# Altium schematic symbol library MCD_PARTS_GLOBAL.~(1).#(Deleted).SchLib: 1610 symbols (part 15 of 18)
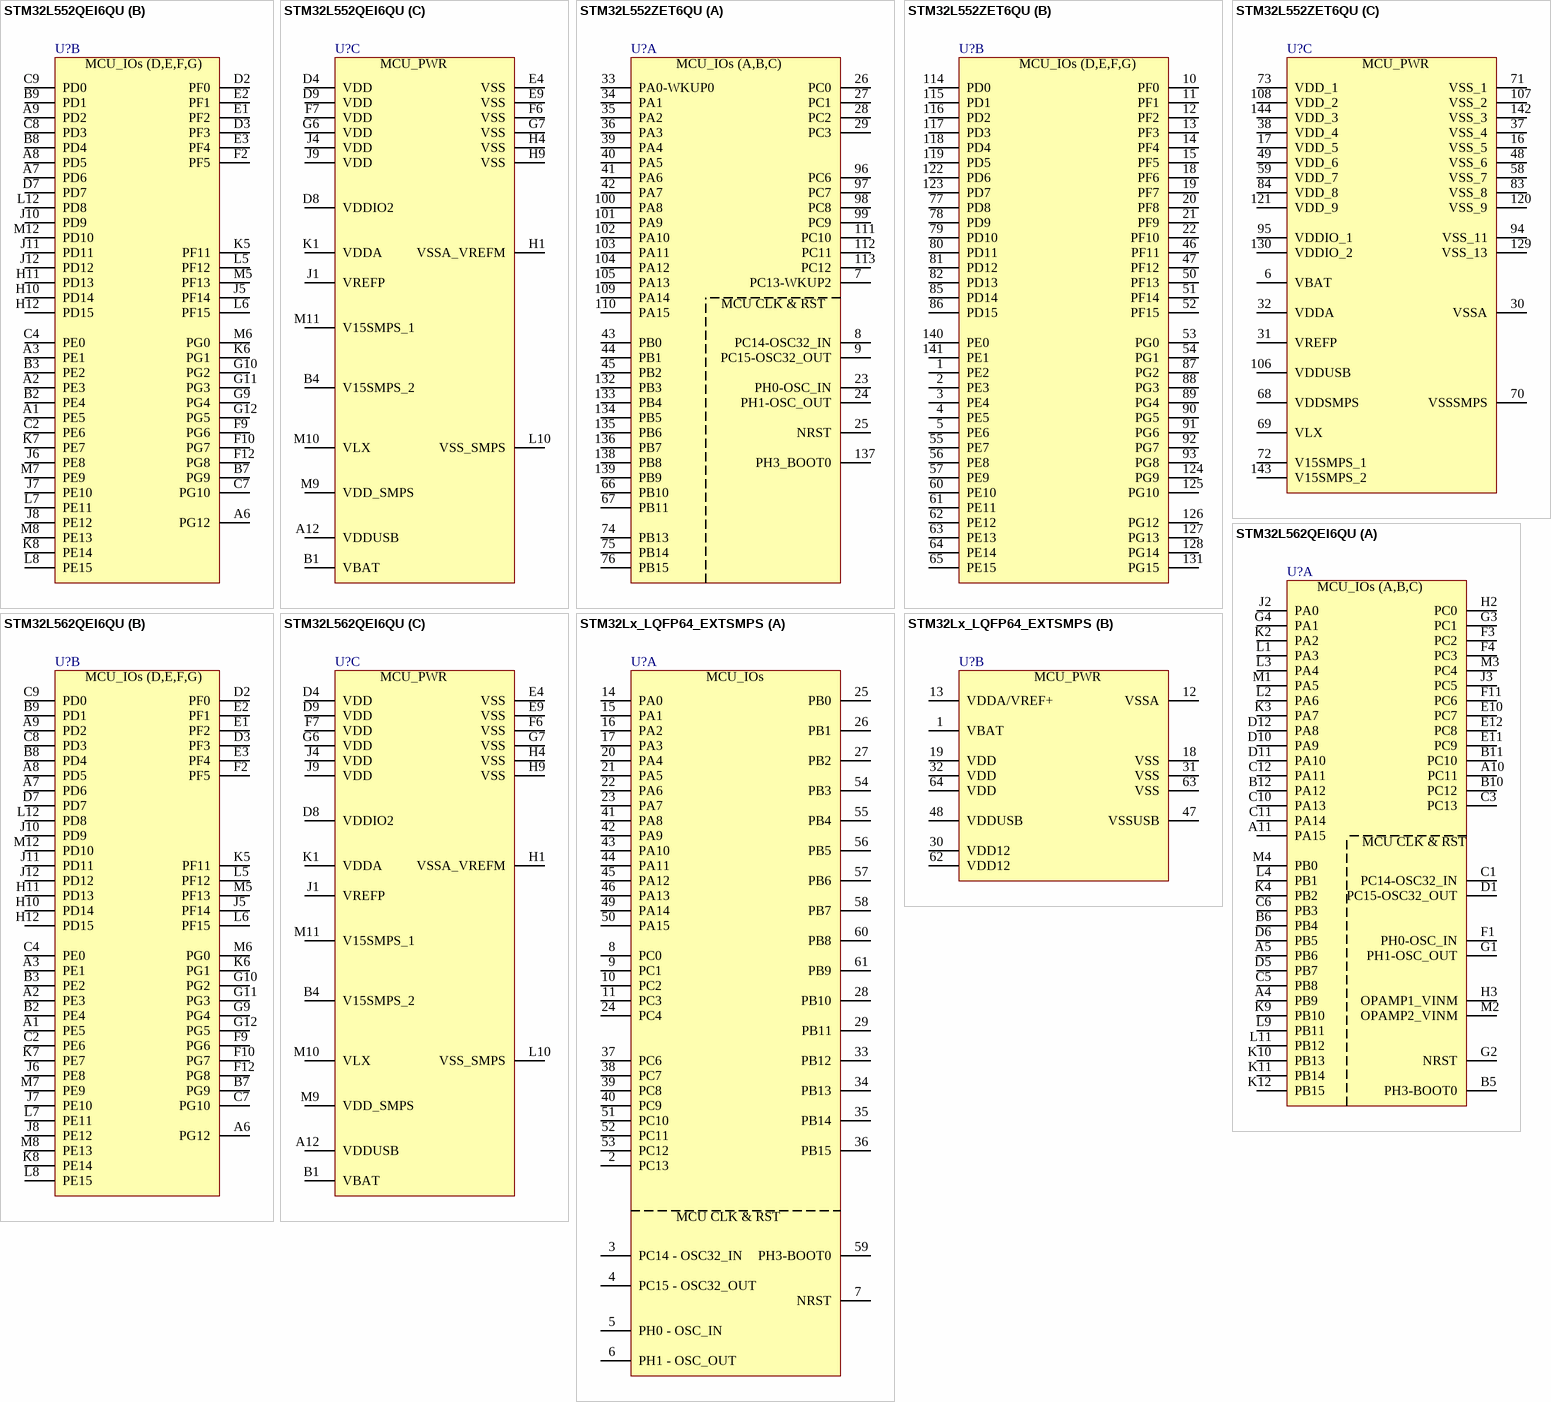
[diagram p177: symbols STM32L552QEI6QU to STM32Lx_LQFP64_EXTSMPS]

## STM32L552ZET6QU
designator U?
part A pins: 7 PC13-WKUP2, 8 PC14-OSC32_IN, 9 PC15-OSC32_OUT, 23 PH0-OSC_IN, 24 PH1-OSC_OUT, 25 NRST, 26 PC0, 27 PC1, 28 PC2, 29 PC3, 33 PA0-WKUP0, 34 PA1, 35 PA2, 36 PA3, 39 PA4, 40 PA5, 41 PA6, 42 PA7, 43 PB0, 44 PB1, 45 PB2, 66 PB10, 67 PB11, 74 PB13, 75 PB14, 76 PB15, 96 PC6, 97 PC7, 98 PC8, 99 PC9, 100 PA8, 101 PA9, 102 PA10, 103 PA11, 104 PA12, 105 PA13, 109 PA14, 110 PA15, 111 PC10, 112 PC11, 113 PC12, 132 PB3, 133 PB4, 134 PB5, 135 PB6, 136 PB7, 137 PH3_BOOT0, 138 PB8, 139 PB9
part B pins: 1 PE2, 2 PE3, 3 PE4, 4 PE5, 5 PE6, 10 PF0, 11 PF1, 12 PF2, 13 PF3, 14 PF4, 15 PF5, 18 PF6, 19 PF7, 20 PF8, 21 PF9, 22 PF10, 46 PF11, 47 PF12, 50 PF13, 51 PF14, 52 PF15, 53 PG0, 54 PG1, 55 PE7, 56 PE8, 57 PE9, 60 PE10, 61 PE11, 62 PE12, 63 PE13, 64 PE14, 65 PE15, 77 PD8, 78 PD9, 79 PD10, 80 PD11, 81 PD12, 82 PD13, 85 PD14, 86 PD15, 87 PG2, 88 PG3, 89 PG4, 90 PG5, 91 PG6, 92 PG7, 93 PG8, 114 PD0, 115 PD1, 116 PD2, 117 PD3, 118 PD4, 119 PD5, 122 PD6, 123 PD7, 124 PG9, 125 PG10, 126 PG12, 127 PG13, 128 PG14, 131 PG15, 140 PE0, 141 PE1
part C pins: 6 VBAT, 16 VSS_5, 17 VDD_5, 30 VSSA, 31 VREFP, 32 VDDA, 37 VSS_4, 38 VDD_4, 48 VSS_6, 49 VDD_6, 58 VSS_7, 59 VDD_7, 68 VDDSMPS, 69 VLX, 70 VSSSMPS, 71 VSS_1, 72 V15SMPS_1, 73 VDD_1, 83 VSS_8, 84 VDD_8, 94 VSS_11, 95 VDDIO_1, 106 VDDUSB, 107 VSS_2, 108 VDD_2, 120 VSS_9, 121 VDD_9, 129 VSS_13, 130 VDDIO_2, 142 VSS_3, 143 V15SMPS_2, 144 VDD_3

## STM32L562QEI6QU
designator U?
part A pins: A4 PB9, A5 PB6, A10 PC11, A11 PA15, B5 PH3-BOOT0, B6 PB4, B10 PC12, B11 PC10, B12 PA12, C1 PC14-OSC32_IN, C3 PC13, C5 PB8, C6 PB3, C10 PA13, C11 PA14, C12 PA11, D1 PC15-OSC32_OUT, D5 PB7, D6 PB5, D10 PA9, D11 PA10, D12 PA8, E10 PC7, E11 PC9, E12 PC8, F1 PH0-OSC_IN, F3 PC2, F4 PC3, F11 PC6, G1 PH1-OSC_OUT, G2 NRST, G3 PC1, G4 PA1, H2 PC0, H3 OPAMP1_VINM, J2 PA0, J3 PC5, K2 PA2, K3 PA7, K4 PB2, K9 PB10, K10 PB13, K11 PB14, K12 PB15, L1 PA3, L2 PA6, L3 PA4, L4 PB1, L9 PB11, L11 PB12, M1 PA5, M2 OPAMP2_VINM, M3 PC4, M4 PB0
part B pins: A1 PE5, A2 PE3, A3 PE1, A6 PG12, A7 PD6, A8 PD5, A9 PD2, B2 PE4, B3 PE2, B7 PG9, B8 PD4, B9 PD1, C2 PE6, C4 PE0, C7 PG10, C8 PD3, C9 PD0, D2 PF0, D3 PF3, D7 PD7, E1 PF2, E2 PF1, E3 PF4, F2 PF5, F9 PG6, F10 PG7, F12 PG8, G9 PG4, G10 PG2, G11 PG3, G12 PG5, H10 PD14, H11 PD13, H12 PD15, J5 PF14, J6 PE8, J7 PE10, J8 PE12, J10 PD9, J11 PD11, J12 PD12, K5 PF11, K6 PG1, K7 PE7, K8 PE14, L5 PF12, L6 PF15, L7 PE11, L8 PE15, L12 PD8, M5 PF13, M6 PG0, M7 PE9, M8 PE13, M12 PD10
part C pins: A12 VDDUSB, B1 VBAT, B4 V15SMPS_2, D4 VDD, D8 VDDIO2, D9 VDD, E4 VSS, E9 VSS, F6 VSS, F7 VDD, G6 VDD, G7 VSS, H1 VSSA_VREFM, H4 VSS, H9 VSS, J1 VREFP, J4 VDD, J9 VDD, K1 VDDA, L10 VSS_SMPS, M9 VDD_SMPS, M10 VLX, M11 V15SMPS_1

## STM32Lx_LQFP64_EXTSMPS
designator U?
part A pins: 2 PC13, 3 PC14 - OSC32_IN, 4 PC15 - OSC32_OUT, 5 PH0 - OSC_IN, 6 PH1 - OSC_OUT, 7 NRST, 8 PC0, 9 PC1, 10 PC2, 11 PC3, 14 PA0, 15 PA1, 16 PA2, 17 PA3, 20 PA4, 21 PA5, 22 PA6, 23 PA7, 24 PC4, 25 PB0, 26 PB1, 27 PB2, 28 PB10, 29 PB11, 33 PB12, 34 PB13, 35 PB14, 36 PB15, 37 PC6, 38 PC7, 39 PC8, 40 PC9, 41 PA8, 42 PA9, 43 PA10, 44 PA11, 45 PA12, 46 PA13, 49 PA14, 50 PA15, 51 PC10, 52 PC11, 53 PC12, 54 PB3, 55 PB4, 56 PB5, 57 PB6, 58 PB7, 59 PH3-BOOT0, 60 PB8, 61 PB9
part B pins: 1 VBAT, 12 VSSA, 13 VDDA/VREF+, 18 VSS, 19 VDD, 30 VDD12, 31 VSS, 32 VDD, 47 VSSUSB, 48 VDDUSB, 62 VDD12, 63 VSS, 64 VDD

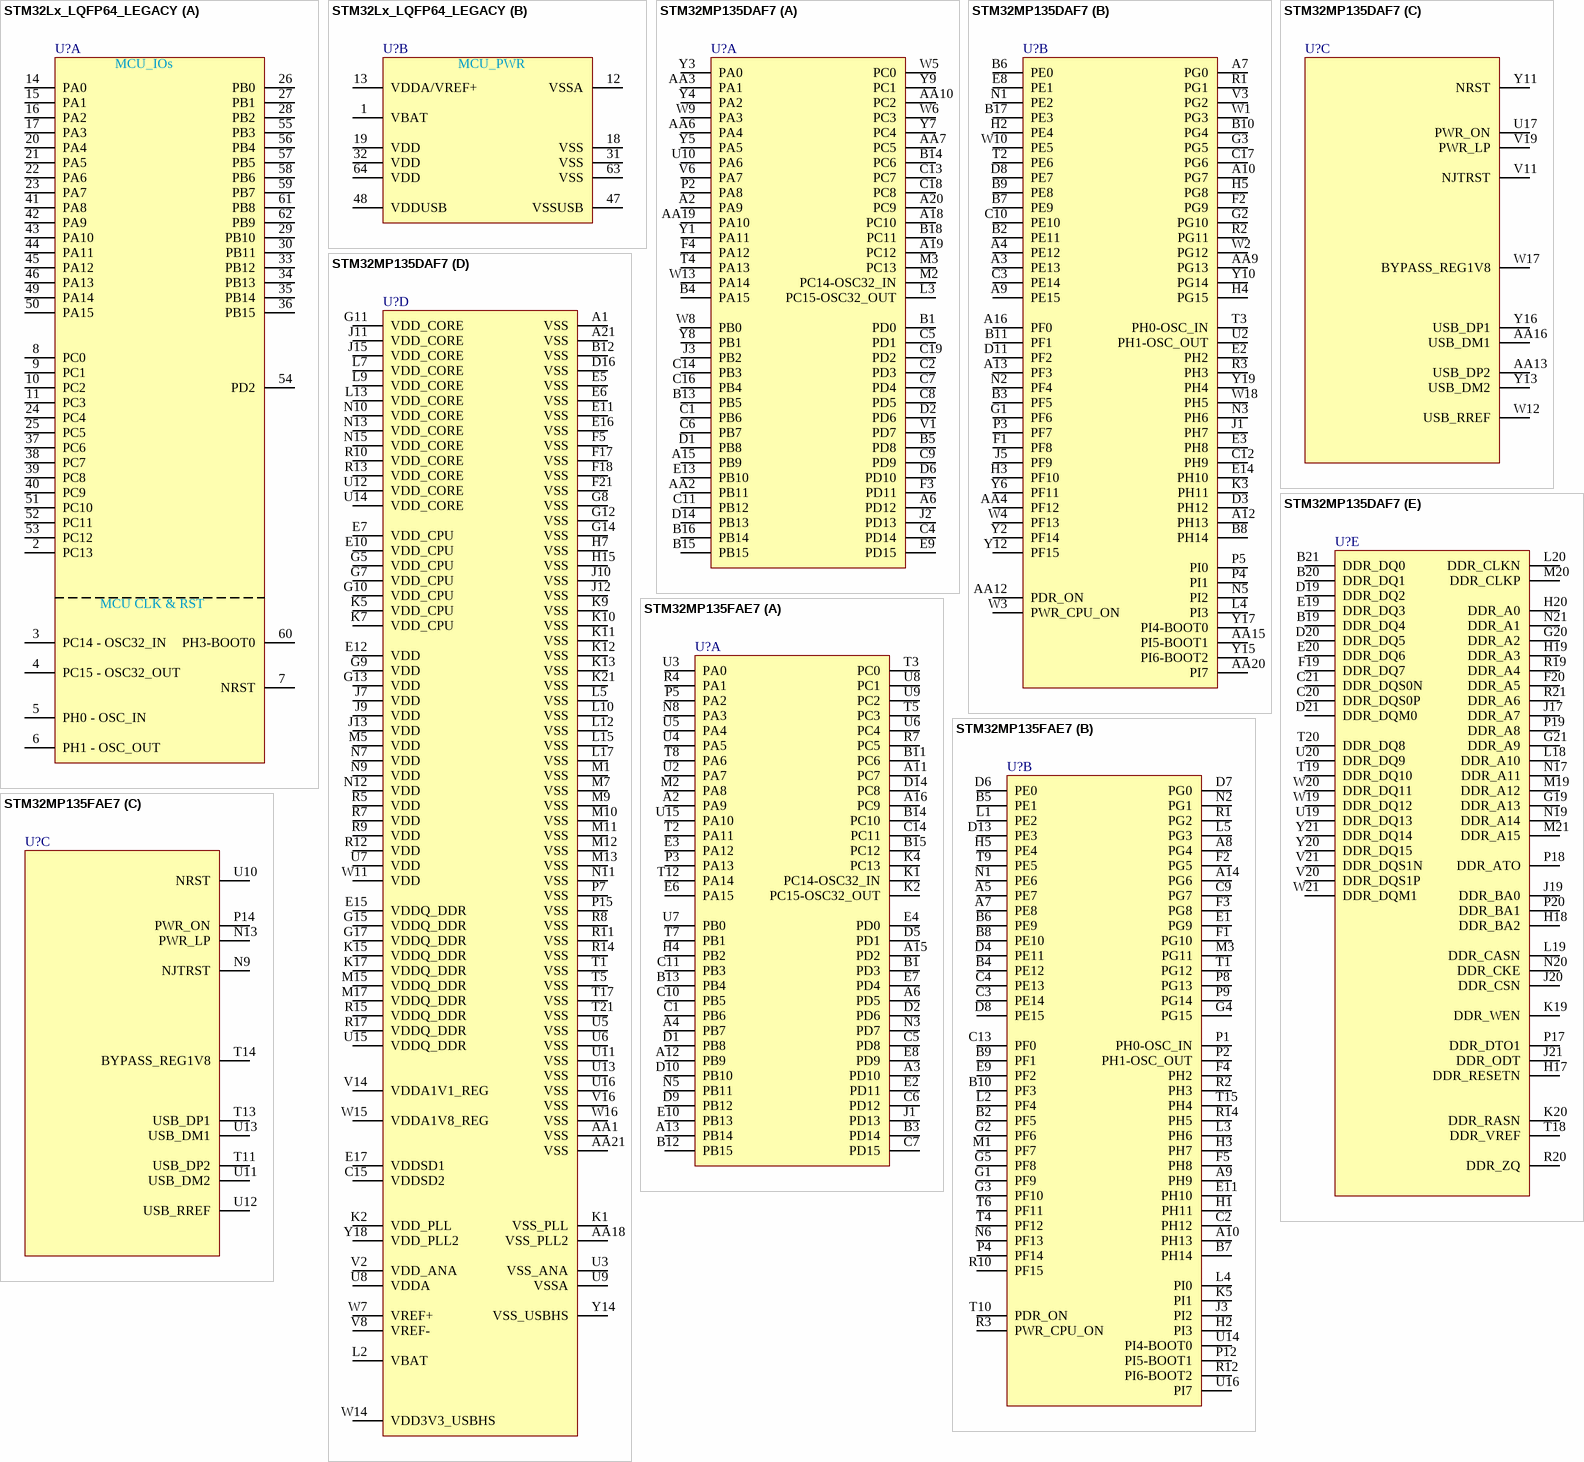
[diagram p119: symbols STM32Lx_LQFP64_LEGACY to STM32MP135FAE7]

## STM32Lx_LQFP64_LEGACY
designator U?
part A pins: 2 PC13, 3 PC14 - OSC32_IN, 4 PC15 - OSC32_OUT, 5 PH0 - OSC_IN, 6 PH1 - OSC_OUT, 7 NRST, 8 PC0, 9 PC1, 10 PC2, 11 PC3, 14 PA0, 15 PA1, 16 PA2, 17 PA3, 20 PA4, 21 PA5, 22 PA6, 23 PA7, 24 PC4, 25 PC5, 26 PB0, 27 PB1, 28 PB2, 29 PB10, 30 PB11, 33 PB12, 34 PB13, 35 PB14, 36 PB15, 37 PC6, 38 PC7, 39 PC8, 40 PC9, 41 PA8, 42 PA9, 43 PA10, 44 PA11, 45 PA12, 46 PA13, 49 PA14, 50 PA15, 51 PC10, 52 PC11, 53 PC12, 54 PD2, 55 PB3, 56 PB4, 57 PB5, 58 PB6, 59 PB7, 60 PH3-BOOT0, 61 PB8, 62 PB9
part B pins: 1 VBAT, 12 VSSA, 13 VDDA/VREF+, 18 VSS, 19 VDD, 31 VSS, 32 VDD, 47 VSSUSB, 48 VDDUSB, 63 VSS, 64 VDD

## STM32MP135DAF7
designator U?
part A pins: A2 PA9, A6 PD12, A15 PB9, A18 PC10, A19 PC12, A20 PC9, AA2 PB11, AA3 PA1, AA6 PA4, AA7 PC5, AA10 PC2, AA19 PA10, B1 PD0, B4 PA15, B5 PD8, B13 PB5, B14 PC6, B15 PB15, B16 PB14, B18 PC11, C1 PB6, C2 PD3, C4 PD14, C5 PD1, C6 PB7, C7 PD4, C8 PD5, C9 PD9, C11 PB12, C13 PC7, C14 PB3, C16 PB4, C18 PC8, C19 PD2, D1 PB8, D2 PD6, D6 PD10, D14 PB13, E9 PD15, E13 PB10, F3 PD11, F4 PA12, J2 PD13, J3 PB2, L3 PC15-OSC32_OUT, M2 PC14-OSC32_IN, M3 PC13, P2 PA8, T4 PA13, U10 PA6, V1 PD7, V6 PA7, W5 PC0, W6 PC3, W8 PB0, W9 PA3, W13 PA14, Y1 PA11, Y3 PA0, Y4 PA2, Y5 PA5, Y7 PC4, Y8 PB1, Y9 PC1
part B pins: A3 PE13, A4 PE12, A7 PG0, A9 PE15, A10 PG7, A12 PH13, A13 PF3, A16 PF0, AA4 PF12, AA9 PG13, AA12 PDR_ON, AA15 PI5-BOOT1, AA20 PI7, B2 PE11, B3 PF5, B6 PE0, B7 PE9, B8 PH14, B9 PE8, B10 PG4, B11 PF1, B17 PE3, C3 PE14, C10 PE10, C12 PH9, C17 PG6, D3 PH12, D8 PE7, D11 PF2, E2 PH2, E3 PH8, E8 PE1, E14 PH10, F1 PF8, F2 PG9, G1 PF6, G2 PG10, G3 PG5, H2 PE4, H3 PF10, H4 PG15, H5 PG8, J1 PH7, J5 PF9, K3 PH11, L4 PI3, N1 PE2, N2 PF4, N3 PH6, N5 PI2, P3 PF7, P4 PI1, P5 PI0, R1 PG1, R2 PG11, R3 PH3, T2 PE6, T3 PH0-OSC_IN, U2 PH1-OSC_OUT, V3 PG2, W1 PG3, W2 PG12, W3 PWR_CPU_ON, W4 PF13, W10 PE5, W18 PH5, Y2 PF14, Y6 PF11, Y10 PG14, Y12 PF15, Y15 PI6-BOOT2, Y17 PI4-BOOT0, Y19 PH4
part C pins: AA13 USB_DP2, AA16 USB_DM1, U17 PWR_ON, V11 NJTRST, V19 PWR_LP, W12 USB_RREF, W17 BYPASS_REG1V8, Y11 NRST, Y13 USB_DM2, Y16 USB_DP1
part D pins: A1 VSS, A21 VSS, AA1 VSS, AA18 VSS_PLL2, AA21 VSS, B12 VSS, C15 VDDSD2, D16 VSS, E5 VSS, E6 VSS, E7 VDD_CPU, E10 VDD_CPU, E11 VSS, E12 VDD, E15 VDDQ_DDR, E16 VSS, E17 VDDSD1, F5 VSS, F17 VSS, F18 VSS, F21 VSS, G5 VDD_CPU, G7 VDD_CPU, G8 VSS, G9 VDD, G10 VDD_CPU, G11 VDD_CORE, G12 VSS, G13 VDD, G14 VSS, G15 VDDQ_DDR, G17 VDDQ_DDR, H7 VSS, H15 VSS, J7 VDD, J9 VDD, J10 VSS, J11 VDD_CORE, J12 VSS, J13 VDD, J15 VDD_CORE, K1 VSS_PLL, K2 VDD_PLL, K5 VDD_CPU, K7 VDD_CPU, K9 VSS, K10 VSS, K11 VSS, K12 VSS, K13 VSS, K15 VDDQ_DDR, K17 VDDQ_DDR, K21 VSS, L2 VBAT, L5 VSS, L7 VDD_CORE, L9 VDD_CORE, L10 VSS, L12 VSS, L13 VDD_CORE, L15 VSS, L17 VSS, M1 VSS, M5 VDD, M7 VSS, M9 VSS, M10 VSS, M11 VSS, M12 VSS, M13 VSS, M15 VDDQ_DDR, M17 VDDQ_DDR, N7 VDD, N9 VDD, N10 VDD_CORE, N11 VSS, N12 VDD, N13 VDD_CORE, N15 VDD_CORE, P7 VSS, P15 VSS, R5 VDD, R7 VDD, R8 VSS, R9 VDD, R10 VDD_CORE, R11 VSS, R12 VDD, R13 VDD_CORE, R14 VSS, R15 VDDQ_DDR, R17 VDDQ_DDR, T1 VSS, T5 VSS, T17 VSS, T21 VSS, U3 VSS_ANA, U5 VSS, U6 VSS, U7 VDD, U8 VDDA, U9 VSSA, U11 VSS, U12 VDD_CORE, U13 VSS, U14 VDD_CORE, U15 VDDQ_DDR, U16 VSS, V2 VDD_ANA, V8 VREF-, V14 VDDA1V1_REG, V16 VSS, W7 VREF+, W11 VDD, W14 VDD3V3_USBHS, W15 VDDA1V8_REG, W16 VSS, Y14 VSS_USBHS, Y18 VDD_PLL2
part E pins: B19 DDR_DQ4, B20 DDR_DQ1, B21 DDR_DQ0, C20 DDR_DQS0P, C21 DDR_DQS0N, D19 DDR_DQ2, D20 DDR_DQ5, D21 DDR_DQM0, E19 DDR_DQ3, E20 DDR_DQ6, F19 DDR_DQ7, F20 DDR_A5, G19 DDR_A13, G20 DDR_A2, G21 DDR_A9, H17 DDR_RESETN, H18 DDR_BA2, H19 DDR_A3, H20 DDR_A0, J17 DDR_A7, J19 DDR_BA0, J20 DDR_CSN, J21 DDR_ODT, K19 DDR_WEN, K20 DDR_RASN, L18 DDR_A10, L19 DDR_CASN, L20 DDR_CLKN, M19 DDR_A12, M20 DDR_CLKP, M21 DDR_A15, N17 DDR_A11, N19 DDR_A14, N20 DDR_CKE, N21 DDR_A1, P17 DDR_DTO1, P18 DDR_ATO, P19 DDR_A8, P20 DDR_BA1, R19 DDR_A4, R20 DDR_ZQ, R21 DDR_A6, T18 DDR_VREF, T19 DDR_DQ10, T20 DDR_DQ8, U19 DDR_DQ13, U20 DDR_DQ9, V20 DDR_DQS1P, V21 DDR_DQS1N, W19 DDR_DQ12, W20 DDR_DQ11, W21 DDR_DQM1, Y20 DDR_DQ15, Y21 DDR_DQ14

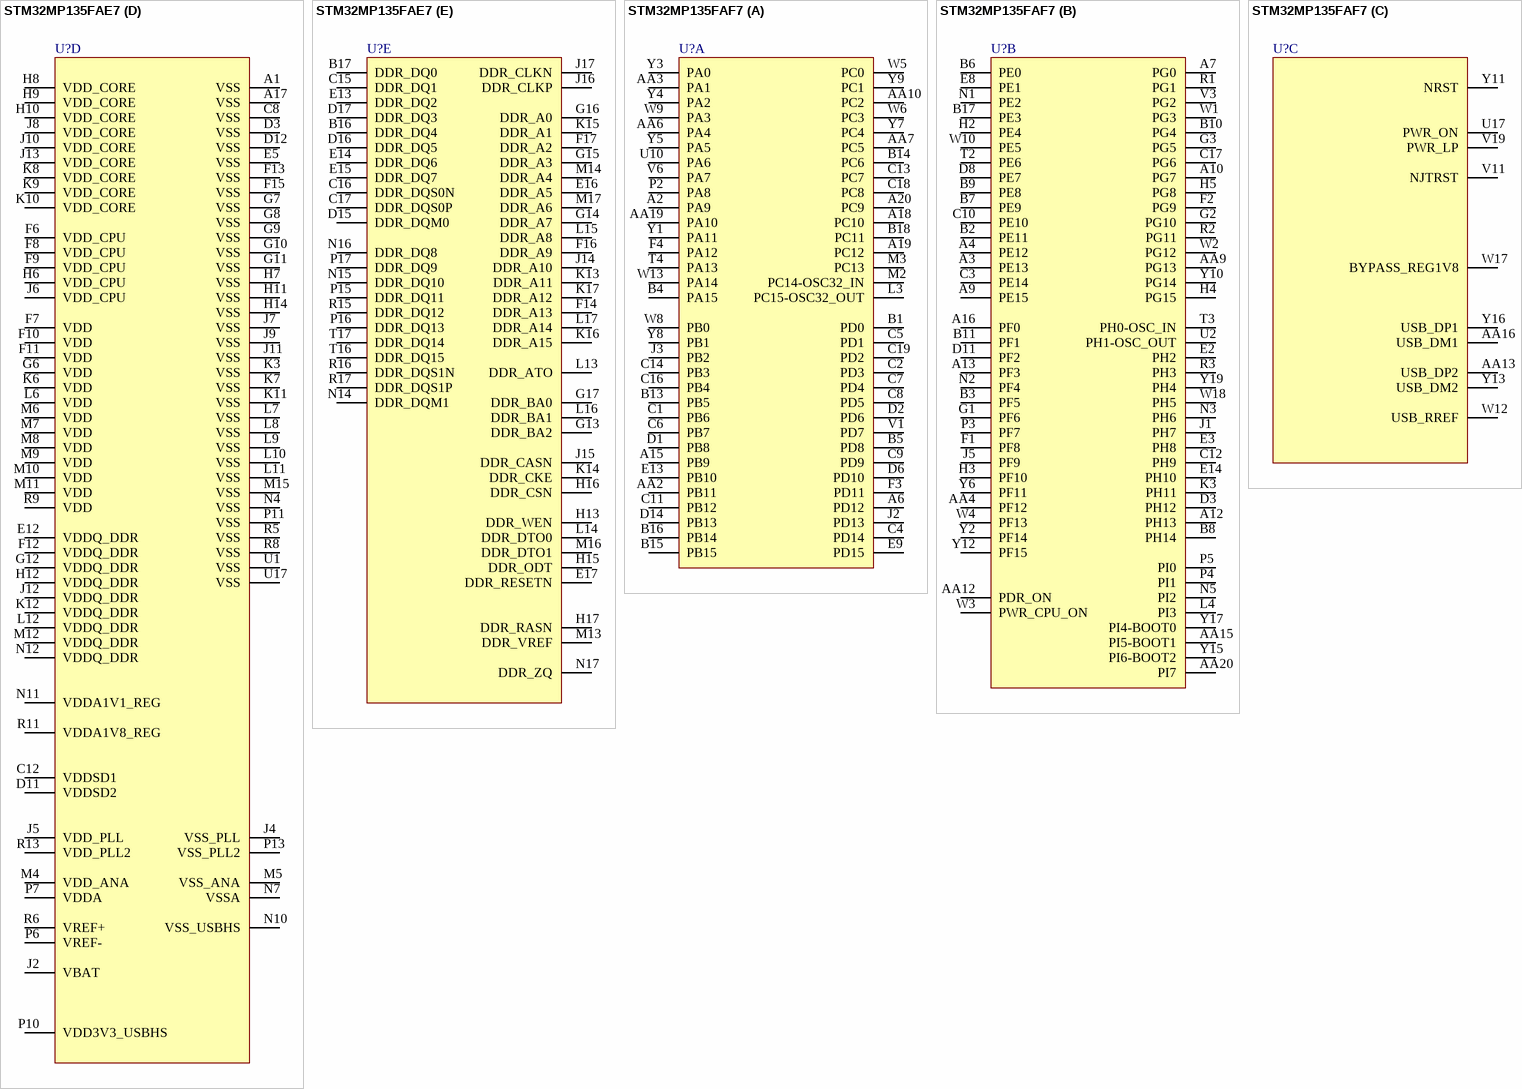
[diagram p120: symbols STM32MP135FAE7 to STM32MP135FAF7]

## STM32MP135FAE7
designator U?
part A pins: A2 PA9, A3 PD10, A4 PB7, A6 PD5, A11 PC7, A12 PB9, A13 PB14, A15 PD2, A16 PC9, B1 PD3, B3 PD14, B11 PC6, B12 PB15, B13 PB4, B14 PC10, B15 PC12, C1 PB6, C5 PD8, C6 PD12, C7 PD15, C10 PB5, C11 PB3, C14 PC11, D1 PB8, D2 PD6, D5 PD1, D9 PB12, D10 PB10, D14 PC8, E2 PD11, E3 PA12, E4 PD0, E6 PA15, E7 PD4, E8 PD9, E10 PB13, H4 PB2, J1 PD13, K1 PC14-OSC32_IN, K2 PC15-OSC32_OUT, K4 PC13, M2 PA8, N3 PD7, N5 PB11, N8 PA3, P3 PA13, P5 PA2, R4 PA1, R7 PC5, T2 PA11, T3 PC0, T5 PC3, T7 PB1, T8 PA6, T12 PA14, U2 PA7, U3 PA0, U4 PA5, U5 PA4, U6 PC4, U7 PB0, U8 PC1, U9 PC2, U15 PA10
part B pins: A5 PE7, A7 PE8, A8 PG4, A9 PH9, A10 PH13, A14 PG6, B2 PF5, B4 PE12, B5 PE1, B6 PE9, B7 PH14, B8 PE10, B9 PF1, B10 PF3, C2 PH12, C3 PE14, C4 PE13, C9 PG7, C13 PF0, D4 PE11, D6 PE0, D7 PG0, D8 PE15, D13 PE3, E1 PG9, E9 PF2, E11 PH10, F1 PG10, F2 PG5, F3 PG8, F4 PH2, F5 PH8, G1 PF9, G2 PF6, G3 PF10, G4 PG15, G5 PF8, H1 PH11, H2 PI3, H3 PH7, H5 PE4, J3 PI2, K5 PI1, L1 PE2, L2 PF4, L3 PH6, L4 PI0, L5 PG3, M1 PF7, M3 PG11, N1 PE6, N2 PG1, N6 PF13, P1 PH0-OSC_IN, P2 PH1-OSC_OUT, P4 PF14, P8 PG13, P9 PG14, P12 PI5-BOOT1, R1 PG2, R2 PH3, R3 PWR_CPU_ON, R10 PF15, R12 PI6-BOOT2, R14 PH5, T1 PG12, T4 PF12, T6 PF11, T9 PE5, T10 PDR_ON, T15 PH4, U14 PI4-BOOT0, U16 PI7
part C pins: N9 NJTRST, N13 PWR_LP, P14 PWR_ON, T11 USB_DP2, T13 USB_DP1, T14 BYPASS_REG1V8, U10 NRST, U11 USB_DM2, U12 USB_RREF, U13 USB_DM1
part D pins: A1 VSS, A17 VSS, C8 VSS, C12 VDDSD1, D3 VSS, D11 VDDSD2, D12 VSS, E5 VSS, E12 VDDQ_DDR, F6 VDD_CPU, F7 VDD, F8 VDD_CPU, F9 VDD_CPU, F10 VDD, F11 VDD, F12 VDDQ_DDR, F13 VSS, F15 VSS, G6 VDD, G7 VSS, G8 VSS, G9 VSS, G10 VSS, G11 VSS, G12 VDDQ_DDR, H6 VDD_CPU, H7 VSS, H8 VDD_CORE, H9 VDD_CORE, H10 VDD_CORE, H11 VSS, H12 VDDQ_DDR, H14 VSS, J2 VBAT, J4 VSS_PLL, J5 VDD_PLL, J6 VDD_CPU, J7 VSS, J8 VDD_CORE, J9 VSS, J10 VDD_CORE, J11 VSS, J12 VDDQ_DDR, J13 VDD_CORE, K3 VSS, K6 VDD, K7 VSS, K8 VDD_CORE, K9 VDD_CORE, K10 VDD_CORE, K11 VSS, K12 VDDQ_DDR, L6 VDD, L7 VSS, L8 VSS, L9 VSS, L10 VSS, L11 VSS, L12 VDDQ_DDR, M4 VDD_ANA, M5 VSS_ANA, M6 VDD, M7 VDD, M8 VDD, M9 VDD, M10 VDD, M11 VDD, M12 VDDQ_DDR, M15 VSS, N4 VSS, N7 VSSA, N10 VSS_USBHS, N11 VDDA1V1_REG, N12 VDDQ_DDR, P6 VREF-, P7 VDDA, P10 VDD3V3_USBHS, P11 VSS, P13 VSS_PLL2, R5 VSS, R6 VREF+, R8 VSS, R9 VDD, R11 VDDA1V8_REG, R13 VDD_PLL2, U1 VSS, U17 VSS
part E pins: B16 DDR_DQ4, B17 DDR_DQ0, C15 DDR_DQ1, C16 DDR_DQS0N, C17 DDR_DQS0P, D15 DDR_DQM0, D16 DDR_DQ5, D17 DDR_DQ3, E13 DDR_DQ2, E14 DDR_DQ6, E15 DDR_DQ7, E16 DDR_A5, E17 DDR_RESETN, F14 DDR_A13, F16 DDR_A9, F17 DDR_A2, G13 DDR_BA2, G14 DDR_A7, G15 DDR_A3, G16 DDR_A0, G17 DDR_BA0, H13 DDR_WEN, H15 DDR_ODT, H16 DDR_CSN, H17 DDR_RASN, J14 DDR_A10, J15 DDR_CASN, J16 DDR_CLKP, J17 DDR_CLKN, K13 DDR_A11, K14 DDR_CKE, K15 DDR_A1, K16 DDR_A15, K17 DDR_A12, L13 DDR_ATO, L14 DDR_DTO0, L15 DDR_A8, L16 DDR_BA1, L17 DDR_A14, M13 DDR_VREF, M14 DDR_A4, M16 DDR_DTO1, M17 DDR_A6, N14 DDR_DQM1, N15 DDR_DQ10, N16 DDR_DQ8, N17 DDR_ZQ, P15 DDR_DQ11, P16 DDR_DQ13, P17 DDR_DQ9, R15 DDR_DQ12, R16 DDR_DQS1N, R17 DDR_DQS1P, T16 DDR_DQ15, T17 DDR_DQ14

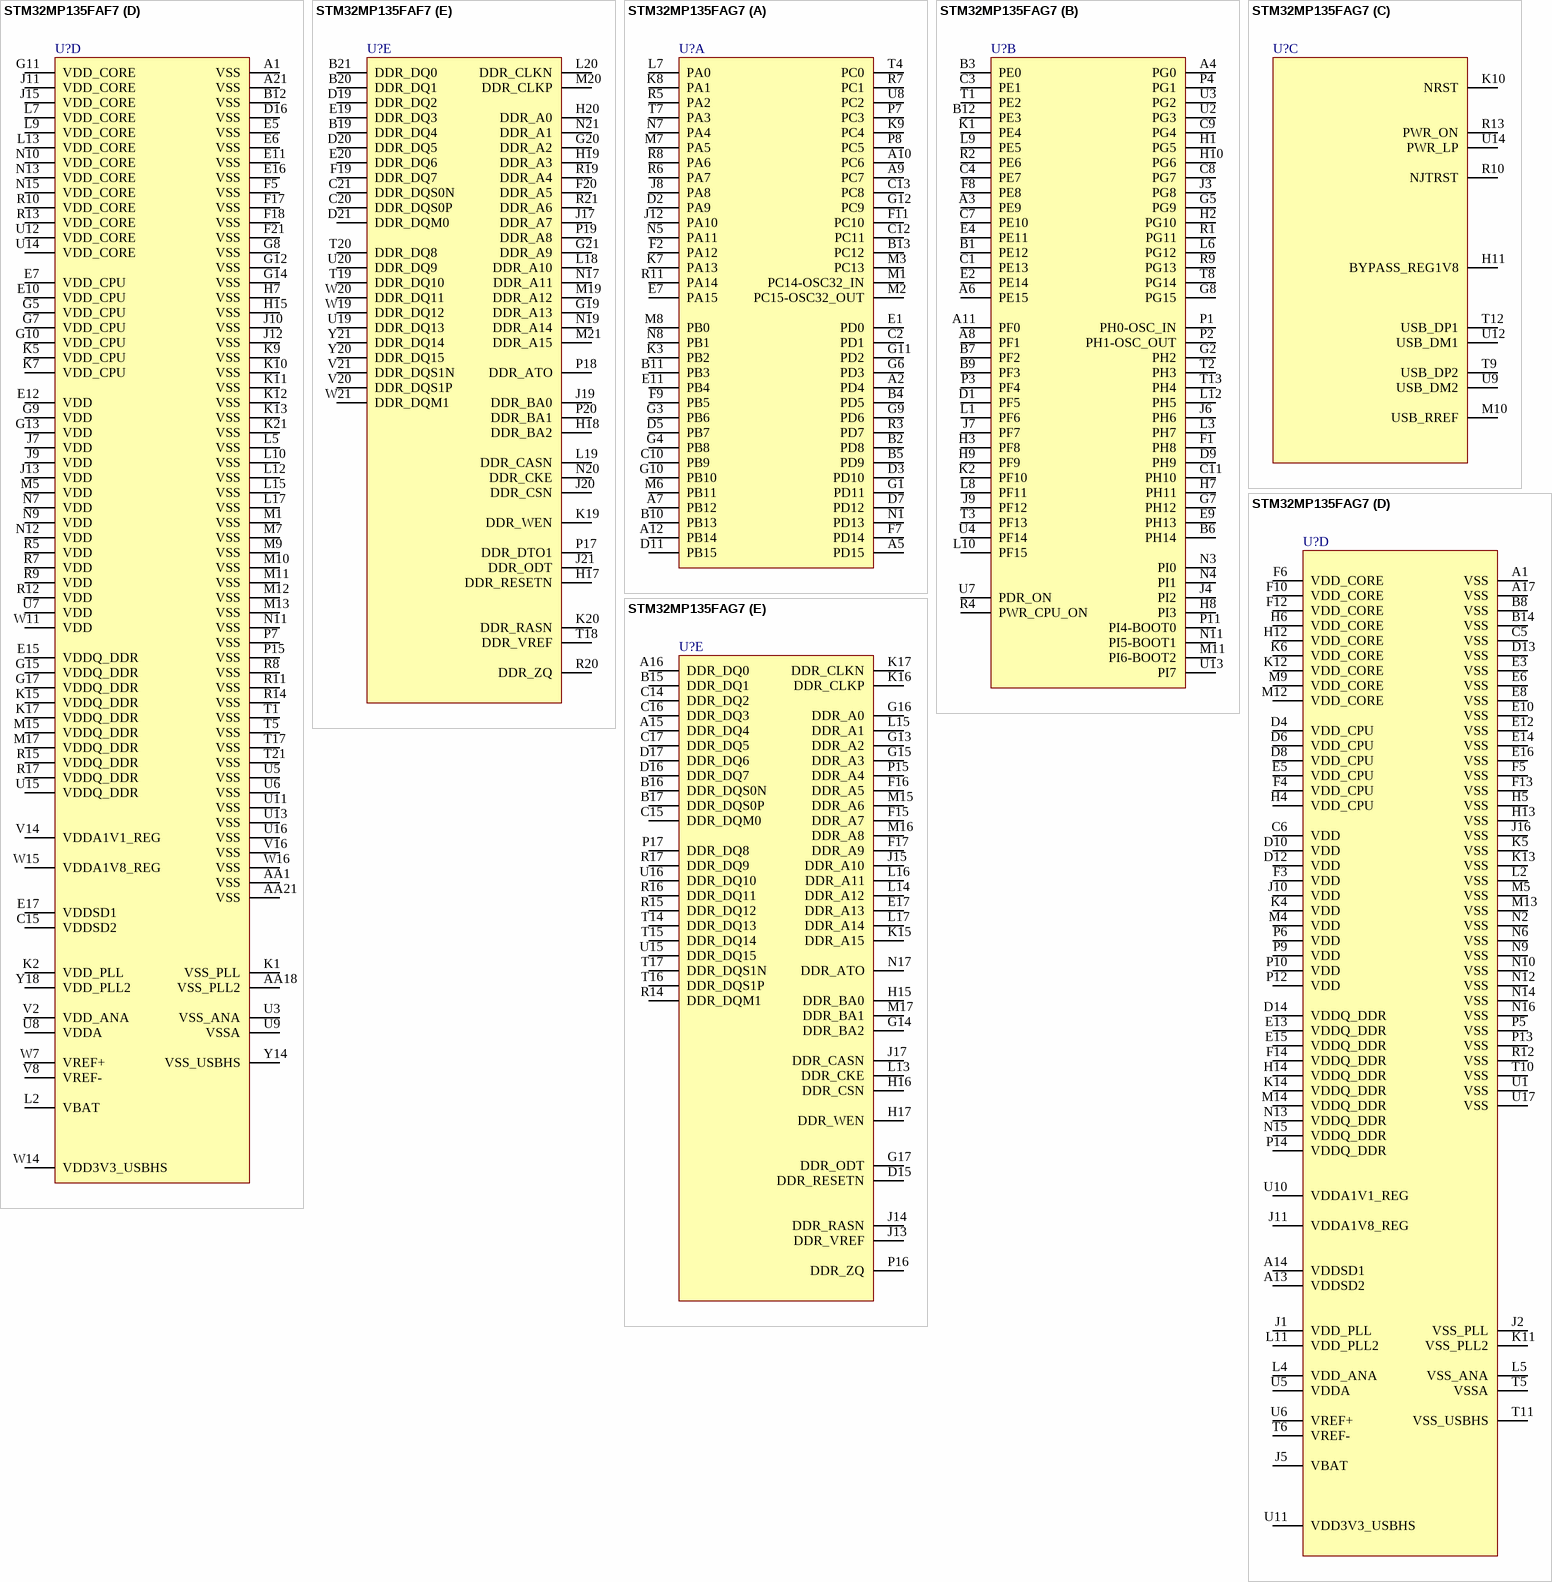
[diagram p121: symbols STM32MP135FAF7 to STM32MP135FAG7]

## STM32MP135FAF7
designator U?
part A pins: A2 PA9, A6 PD12, A15 PB9, A18 PC10, A19 PC12, A20 PC9, AA2 PB11, AA3 PA1, AA6 PA4, AA7 PC5, AA10 PC2, AA19 PA10, B1 PD0, B4 PA15, B5 PD8, B13 PB5, B14 PC6, B15 PB15, B16 PB14, B18 PC11, C1 PB6, C2 PD3, C4 PD14, C5 PD1, C6 PB7, C7 PD4, C8 PD5, C9 PD9, C11 PB12, C13 PC7, C14 PB3, C16 PB4, C18 PC8, C19 PD2, D1 PB8, D2 PD6, D6 PD10, D14 PB13, E9 PD15, E13 PB10, F3 PD11, F4 PA12, J2 PD13, J3 PB2, L3 PC15-OSC32_OUT, M2 PC14-OSC32_IN, M3 PC13, P2 PA8, T4 PA13, U10 PA6, V1 PD7, V6 PA7, W5 PC0, W6 PC3, W8 PB0, W9 PA3, W13 PA14, Y1 PA11, Y3 PA0, Y4 PA2, Y5 PA5, Y7 PC4, Y8 PB1, Y9 PC1
part B pins: A3 PE13, A4 PE12, A7 PG0, A9 PE15, A10 PG7, A12 PH13, A13 PF3, A16 PF0, AA4 PF12, AA9 PG13, AA12 PDR_ON, AA15 PI5-BOOT1, AA20 PI7, B2 PE11, B3 PF5, B6 PE0, B7 PE9, B8 PH14, B9 PE8, B10 PG4, B11 PF1, B17 PE3, C3 PE14, C10 PE10, C12 PH9, C17 PG6, D3 PH12, D8 PE7, D11 PF2, E2 PH2, E3 PH8, E8 PE1, E14 PH10, F1 PF8, F2 PG9, G1 PF6, G2 PG10, G3 PG5, H2 PE4, H3 PF10, H4 PG15, H5 PG8, J1 PH7, J5 PF9, K3 PH11, L4 PI3, N1 PE2, N2 PF4, N3 PH6, N5 PI2, P3 PF7, P4 PI1, P5 PI0, R1 PG1, R2 PG11, R3 PH3, T2 PE6, T3 PH0-OSC_IN, U2 PH1-OSC_OUT, V3 PG2, W1 PG3, W2 PG12, W3 PWR_CPU_ON, W4 PF13, W10 PE5, W18 PH5, Y2 PF14, Y6 PF11, Y10 PG14, Y12 PF15, Y15 PI6-BOOT2, Y17 PI4-BOOT0, Y19 PH4
part C pins: AA13 USB_DP2, AA16 USB_DM1, U17 PWR_ON, V11 NJTRST, V19 PWR_LP, W12 USB_RREF, W17 BYPASS_REG1V8, Y11 NRST, Y13 USB_DM2, Y16 USB_DP1
part D pins: A1 VSS, A21 VSS, AA1 VSS, AA18 VSS_PLL2, AA21 VSS, B12 VSS, C15 VDDSD2, D16 VSS, E5 VSS, E6 VSS, E7 VDD_CPU, E10 VDD_CPU, E11 VSS, E12 VDD, E15 VDDQ_DDR, E16 VSS, E17 VDDSD1, F5 VSS, F17 VSS, F18 VSS, F21 VSS, G5 VDD_CPU, G7 VDD_CPU, G8 VSS, G9 VDD, G10 VDD_CPU, G11 VDD_CORE, G12 VSS, G13 VDD, G14 VSS, G15 VDDQ_DDR, G17 VDDQ_DDR, H7 VSS, H15 VSS, J7 VDD, J9 VDD, J10 VSS, J11 VDD_CORE, J12 VSS, J13 VDD, J15 VDD_CORE, K1 VSS_PLL, K2 VDD_PLL, K5 VDD_CPU, K7 VDD_CPU, K9 VSS, K10 VSS, K11 VSS, K12 VSS, K13 VSS, K15 VDDQ_DDR, K17 VDDQ_DDR, K21 VSS, L2 VBAT, L5 VSS, L7 VDD_CORE, L9 VDD_CORE, L10 VSS, L12 VSS, L13 VDD_CORE, L15 VSS, L17 VSS, M1 VSS, M5 VDD, M7 VSS, M9 VSS, M10 VSS, M11 VSS, M12 VSS, M13 VSS, M15 VDDQ_DDR, M17 VDDQ_DDR, N7 VDD, N9 VDD, N10 VDD_CORE, N11 VSS, N12 VDD, N13 VDD_CORE, N15 VDD_CORE, P7 VSS, P15 VSS, R5 VDD, R7 VDD, R8 VSS, R9 VDD, R10 VDD_CORE, R11 VSS, R12 VDD, R13 VDD_CORE, R14 VSS, R15 VDDQ_DDR, R17 VDDQ_DDR, T1 VSS, T5 VSS, T17 VSS, T21 VSS, U3 VSS_ANA, U5 VSS, U6 VSS, U7 VDD, U8 VDDA, U9 VSSA, U11 VSS, U12 VDD_CORE, U13 VSS, U14 VDD_CORE, U15 VDDQ_DDR, U16 VSS, V2 VDD_ANA, V8 VREF-, V14 VDDA1V1_REG, V16 VSS, W7 VREF+, W11 VDD, W14 VDD3V3_USBHS, W15 VDDA1V8_REG, W16 VSS, Y14 VSS_USBHS, Y18 VDD_PLL2
part E pins: B19 DDR_DQ4, B20 DDR_DQ1, B21 DDR_DQ0, C20 DDR_DQS0P, C21 DDR_DQS0N, D19 DDR_DQ2, D20 DDR_DQ5, D21 DDR_DQM0, E19 DDR_DQ3, E20 DDR_DQ6, F19 DDR_DQ7, F20 DDR_A5, G19 DDR_A13, G20 DDR_A2, G21 DDR_A9, H17 DDR_RESETN, H18 DDR_BA2, H19 DDR_A3, H20 DDR_A0, J17 DDR_A7, J19 DDR_BA0, J20 DDR_CSN, J21 DDR_ODT, K19 DDR_WEN, K20 DDR_RASN, L18 DDR_A10, L19 DDR_CASN, L20 DDR_CLKN, M19 DDR_A12, M20 DDR_CLKP, M21 DDR_A15, N17 DDR_A11, N19 DDR_A14, N20 DDR_CKE, N21 DDR_A1, P17 DDR_DTO1, P18 DDR_ATO, P19 DDR_A8, P20 DDR_BA1, R19 DDR_A4, R20 DDR_ZQ, R21 DDR_A6, T18 DDR_VREF, T19 DDR_DQ10, T20 DDR_DQ8, U19 DDR_DQ13, U20 DDR_DQ9, V20 DDR_DQS1P, V21 DDR_DQS1N, W19 DDR_DQ12, W20 DDR_DQ11, W21 DDR_DQM1, Y20 DDR_DQ15, Y21 DDR_DQ14

## STM32MP135FAG7
designator U?
part A pins: A2 PD4, A5 PD15, A7 PB12, A9 PC7, A10 PC6, A12 PB14, B2 PD8, B4 PD5, B5 PD9, B10 PB13, B11 PB3, B13 PC12, C2 PD1, C10 PB9, C12 PC11, C13 PC8, D2 PA9, D3 PD10, D5 PB7, D7 PD12, D11 PB15, E1 PD0, E7 PA15, E11 PB4, F2 PA12, F7 PD14, F9 PB5, F11 PC10, G1 PD11, G3 PB6, G4 PB8, G6 PD3, G9 PD6, G10 PB10, G11 PD2, G12 PC9, J8 PA8, J12 PA10, K3 PB2, K7 PA13, K8 PA1, K9 PC4, L7 PA0, M1 PC14-OSC32_IN, M2 PC15-OSC32_OUT, M3 PC13, M6 PB11, M7 PA5, M8 PB0, N1 PD13, N5 PA11, N7 PA4, N8 PB1, P7 PC3, P8 PC5, R3 PD7, R5 PA2, R6 PA7, R7 PC1, R8 PA6, R11 PA14, T4 PC0, T7 PA3, U8 PC2
part B pins: A3 PE9, A4 PG0, A6 PE15, A8 PF1, A11 PF0, B1 PE12, B3 PE0, B6 PH14, B7 PF2, B9 PF3, B12 PE3, C1 PE13, C3 PE1, C4 PE7, C7 PE10, C8 PG7, C9 PG4, C11 PH10, D1 PF5, D9 PH9, E2 PE14, E4 PE11, E9 PH13, F1 PH8, F8 PE8, G2 PH2, G5 PG9, G7 PH12, G8 PG15, H1 PG5, H2 PG10, H3 PF8, H7 PH11, H8 PI3, H9 PF9, H10 PG6, J3 PG8, J4 PI2, J6 PH6, J7 PF7, J9 PF12, K1 PE4, K2 PF10, L1 PF6, L3 PH7, L6 PG12, L8 PF11, L9 PE5, L10 PF15, L12 PH5, M11 PI6-BOOT2, N3 PI0, N4 PI1, N11 PI5-BOOT1, P1 PH0-OSC_IN, P2 PH1-OSC_OUT, P3 PF4, P4 PG1, P11 PI4-BOOT0, R1 PG11, R2 PE6, R4 PWR_CPU_ON, R9 PG13, T1 PE2, T2 PH3, T3 PF13, T8 PG14, T13 PH4, U2 PG3, U3 PG2, U4 PF14, U7 PDR_ON, U13 PI7
part C pins: H11 BYPASS_REG1V8, K10 NRST, M10 USB_RREF, R10 NJTRST, R13 PWR_ON, T9 USB_DP2, T12 USB_DP1, U9 USB_DM2, U12 USB_DM1, U14 PWR_LP
part D pins: A1 VSS, A13 VDDSD2, A14 VDDSD1, A17 VSS, B8 VSS, B14 VSS, C5 VSS, C6 VDD, D4 VDD_CPU, D6 VDD_CPU, D8 VDD_CPU, D10 VDD, D12 VDD, D13 VSS, D14 VDDQ_DDR, E3 VSS, E5 VDD_CPU, E6 VSS, E8 VSS, E10 VSS, E12 VSS, E13 VDDQ_DDR, E14 VSS, E15 VDDQ_DDR, E16 VSS, F3 VDD, F4 VDD_CPU, F5 VSS, F6 VDD_CORE, F10 VDD_CORE, F12 VDD_CORE, F13 VSS, F14 VDDQ_DDR, H4 VDD_CPU, H5 VSS, H6 VDD_CORE, H12 VDD_CORE, H13 VSS, H14 VDDQ_DDR, J1 VDD_PLL, J2 VSS_PLL, J5 VBAT, J10 VDD, J11 VDDA1V8_REG, J16 VSS, K4 VDD, K5 VSS, K6 VDD_CORE, K11 VSS_PLL2, K12 VDD_CORE, K13 VSS, K14 VDDQ_DDR, L2 VSS, L4 VDD_ANA, L5 VSS_ANA, L11 VDD_PLL2, M4 VDD, M5 VSS, M9 VDD_CORE, M12 VDD_CORE, M13 VSS, M14 VDDQ_DDR, N2 VSS, N6 VSS, N9 VSS, N10 VSS, N12 VSS, N13 VDDQ_DDR, N14 VSS, N15 VDDQ_DDR, N16 VSS, P5 VSS, P6 VDD, P9 VDD, P10 VDD, P12 VDD, P13 VSS, P14 VDDQ_DDR (power), R12 VSS, T5 VSSA, T6 VREF-, T10 VSS, T11 VSS_USBHS, U1 VSS, U5 VDDA, U6 VREF+, U10 VDDA1V1_REG, U11 VDD3V3_USBHS, U17 VSS
part E pins: A15 DDR_DQ4, A16 DDR_DQ0, B15 DDR_DQ1, B16 DDR_DQS0N, B17 DDR_DQS0P, C14 DDR_DQ2, C15 DDR_DQM0, C16 DDR_DQ3, C17 DDR_DQ5, D15 DDR_RESETN, D16 DDR_DQ7, D17 DDR_DQ6, E17 DDR_A13, F15 DDR_A7, F16 DDR_A5, F17 DDR_A9, G13 DDR_A2, G14 DDR_BA2, G15 DDR_A3, G16 DDR_A0, G17 DDR_ODT, H15 DDR_BA0, H16 DDR_CSN, H17 DDR_WEN, J13 DDR_VREF, J14 DDR_RASN, J15 DDR_A10, J17 DDR_CASN, K15 DDR_A15, K16 DDR_CLKP, K17 DDR_CLKN, L13 DDR_CKE, L14 DDR_A12, L15 DDR_A1, L16 DDR_A11, L17 DDR_A14, M15 DDR_A6, M16 DDR_A8, M17 DDR_BA1, N17 DDR_ATO, P15 DDR_A4, P16 DDR_ZQ, P17 DDR_DQ8, R14 DDR_DQM1, R15 DDR_DQ12, R16 DDR_DQ11, R17 DDR_DQ9, T14 DDR_DQ13, T15 DDR_DQ14, T16 DDR_DQS1P, T17 DDR_DQS1N, U15 DDR_DQ15, U16 DDR_DQ10

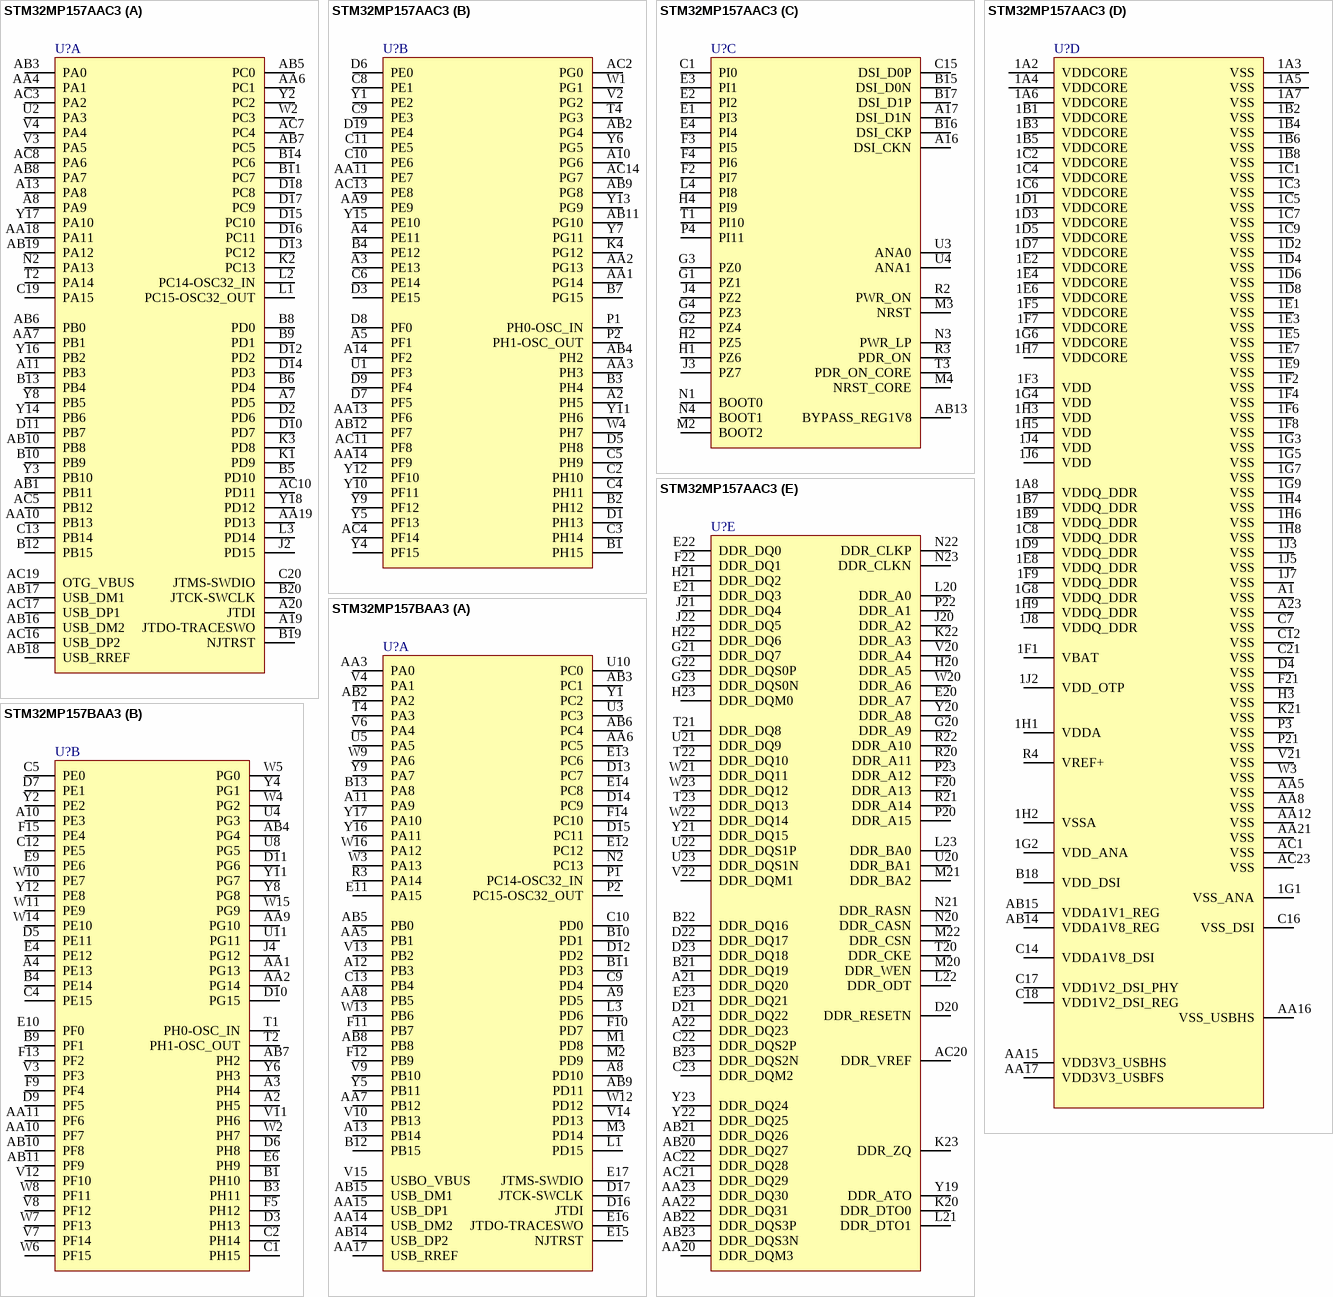
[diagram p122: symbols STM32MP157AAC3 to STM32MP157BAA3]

## STM32MP157AAC3
designator U?
part A pins: A7 PD5, A8 PA9, A11 PB3, A13 PA8, A19 JTDO-TRACESWO, A20 JTDI, AA4 PA1, AA6 PC1, AA7 PB1, AA10 PB13, AA18 PA11, AA19 PD13, AB1 PB11, AB3 PA0, AB5 PC0, AB6 PB0, AB7 PC5, AB8 PA7, AB10 PB8, AB16 USB_DM2, AB17 USB_DM1, AB18 USB_RREF, AB19 PA12, AC3 PA2, AC5 PB12, AC7 PC4, AC8 PA6, AC10 PD11, AC16 USB_DP2, AC17 USB_DP1, AC19 OTG_VBUS, B5 PD10, B6 PD4, B8 PD0, B9 PD1, B10 PB9, B11 PC7, B12 PB15, B13 PB4, B14 PC6, B19 NJTRST, B20 JTCK-SWCLK, C13 PB14, C19 PA15, C20 JTMS-SWDIO, D2 PD6, D10 PD7, D11 PB7, D12 PD2, D13 PC12, D14 PD3, D15 PC10, D16 PC11, D17 PC9, D18 PC8, J2 PD15, K1 PD9, K2 PC13, K3 PD8, L1 PC15-OSC32_OUT, L2 PC14-OSC32_IN, L3 PD14, N2 PA13, T2 PA14, U2 PA3, V3 PA5, V4 PA4, W2 PC3, Y2 PC2, Y3 PB10, Y8 PB5, Y14 PB6, Y16 PB2, Y17 PA10, Y18 PD12
part B pins: A2 PH5, A3 PE13, A4 PE11, A5 PF1, A10 PG6, A14 PF2, AA1 PG14, AA2 PG13, AA3 PH3, AA9 PE9, AA11 PE7, AA13 PF6, AA14 PF9, AB2 PG4, AB4 PH2, AB9 PG8, AB11 PG10, AB12 PF7, AC2 PG0, AC4 PF14, AC11 PF8, AC13 PE8, AC14 PG7, B1 PH15, B2 PH12, B3 PH4, B4 PE12, B7 PG15, C2 PH10, C3 PH14, C4 PH11, C5 PH9, C6 PE14, C8 PE1, C9 PE3, C10 PE6, C11 PE5, D1 PH13, D3 PE15, D5 PH8, D6 PE0, D7 PF5, D8 PF0, D9 PF4, D19 PE4, K4 PG12, P1 PH0-OSC_IN, P2 PH1-OSC_OUT, T4 PG3, U1 PF3, V2 PG2, W1 PG1, W4 PH7, Y1 PE2, Y4 PF15, Y5 PF13, Y6 PG5, Y7 PG11, Y9 PF12, Y10 PF11, Y11 PH6, Y12 PF10, Y13 PG9, Y15 PE10
part C pins: A16 DSI_CKN, A17 DSI_D1N, AB13 BYPASS_REG1V8, B15 DSI_D0N, B16 DSI_CKP, B17 DSI_D1P, C1 PI0, C15 DSI_D0P, E1 PI3, E2 PI2, E3 PI1, E4 PI4, F2 PI7, F3 PI5, F4 PI6, G1 PZ1, G2 PZ4, G3 PZ0, G4 PZ3, H1 PZ6, H2 PZ5, H4 PI9, J3 PZ7, J4 PZ2, L4 PI8, M2 BOOT2, M3 NRST, M4 NRST_CORE, N1 BOOT0, N3 PWR_LP, N4 BOOT1, P4 PI11, R2 PWR_ON, R3 PDR_ON, T1 PI10, T3 PDR_ON_CORE, U3 ANA0, U4 ANA1
part D pins: 1A2 VDDCORE, 1A3 VSS, 1A4 VDDCORE, 1A5 VSS, 1A6 VDDCORE, 1A7 VSS, 1A8 VDDQ_DDR, 1B1 VDDCORE, 1B2 VSS, 1B3 VDDCORE, 1B4 VSS, 1B5 VDDCORE, 1B6 VSS, 1B7 VDDQ_DDR, 1B8 VSS, 1B9 VDDQ_DDR, 1C1 VSS, 1C2 VDDCORE, 1C3 VSS, 1C4 VDDCORE, 1C5 VSS, 1C6 VDDCORE, 1C7 VSS, 1C8 VDDQ_DDR, 1C9 VSS, 1D1 VDDCORE, 1D2 VSS, 1D3 VDDCORE, 1D4 VSS, 1D5 VDDCORE, 1D6 VSS, 1D7 VDDCORE, 1D8 VSS, 1D9 VDDQ_DDR, 1E1 VSS, 1E2 VDDCORE, 1E3 VSS, 1E4 VDDCORE, 1E5 VSS, 1E6 VDDCORE, 1E7 VSS, 1E8 VDDQ_DDR, 1E9 VSS, 1F1 VBAT, 1F2 VSS, 1F3 VDD, 1F4 VSS, 1F5 VDDCORE, 1F6 VSS, 1F7 VDDCORE, 1F8 VSS, 1F9 VDDQ_DDR, 1G1 VSS_ANA, 1G2 VDD_ANA, 1G3 VSS, 1G4 VDD, 1G5 VSS, 1G6 VDDCORE, 1G7 VSS, 1G8 VDDQ_DDR, 1G9 VSS, 1H1 VDDA, 1H2 VSSA, 1H3 VDD, 1H4 VSS, 1H5 VDD, 1H6 VSS, 1H7 VDDCORE, 1H8 VSS, 1H9 VDDQ_DDR, 1J2 VDD_OTP, 1J3 VSS, 1J4 VDD, 1J5 VSS, 1J6 VDD, 1J7 VSS, 1J8 VDDQ_DDR, A1 VSS, A23 VSS, AA5 VSS, AA8 VSS, AA12 VSS, AA15 VDD3V3_USBHS, AA16 VSS_USBHS, AA17 VDD3V3_USBFS, AA21 VSS, AB14 VDDA1V8_REG, AB15 VDDA1V1_REG, AC1 VSS, AC23 VSS, B18 VDD_DSI, C7 VSS, C12 VSS, C14 VDDA1V8_DSI, C16 VSS_DSI, C17 VDD1V2_DSI_PHY, C18 VDD1V2_DSI_REG, C21 VSS, D4 VSS, F21 VSS, H3 VSS, K21 VSS, P3 VSS, P21 VSS, R4 VREF+, V21 VSS, W3 VSS
part E pins: A21 DDR_DQ20, A22 DDR_DQ23, AA20 DDR_DQM3, AA22 DDR_DQ31, AA23 DDR_DQ30, AB20 DDR_DQ27, AB21 DDR_DQ26, AB22 DDR_DQS3P, AB23 DDR_DQS3N, AC20 DDR_VREF, AC21 DDR_DQ29, AC22 DDR_DQ28, B21 DDR_DQ19, B22 DDR_DQ16, B23 DDR_DQS2N, C22 DDR_DQS2P, C23 DDR_DQM2, D20 DDR_RESETN, D21 DDR_DQ22, D22 DDR_DQ17, D23 DDR_DQ18, E20 DDR_A7, E21 DDR_DQ3, E22 DDR_DQ0, E23 DDR_DQ21, F20 DDR_A13, F22 DDR_DQ1, G20 DDR_A9, G21 DDR_DQ7, G22 DDR_DQS0P, G23 DDR_DQS0N, H20 DDR_A5, H21 DDR_DQ2, H22 DDR_DQ6, H23 DDR_DQM0, J20 DDR_A2, J21 DDR_DQ4, J22 DDR_DQ5, K20 DDR_DTO0, K22 DDR_A3, K23 DDR_ZQ, L20 DDR_A0, L21 DDR_DTO1, L22 DDR_ODT, L23 DDR_BA0, M20 DDR_WEN, M21 DDR_BA2, M22 DDR_CSN, N20 DDR_CASN, N21 DDR_RASN, N22 DDR_CLKP, N23 DDR_CLKN, P20 DDR_A15, P22 DDR_A1, P23 DDR_A12, R20 DDR_A11, R21 DDR_A14, R22 DDR_A10, T20 DDR_CKE, T21 DDR_DQ8, T22 DDR_DQ10, T23 DDR_DQ13, U20 DDR_BA1, U21 DDR_DQ9, U22 DDR_DQS1P, U23 DDR_DQS1N, V20 DDR_A4, V22 DDR_DQM1, W20 DDR_A6, W21 DDR_DQ11, W22 DDR_DQ14, W23 DDR_DQ12, Y19 DDR_ATO, Y20 DDR_A8, Y21 DDR_DQ15, Y22 DDR_DQ25, Y23 DDR_DQ24

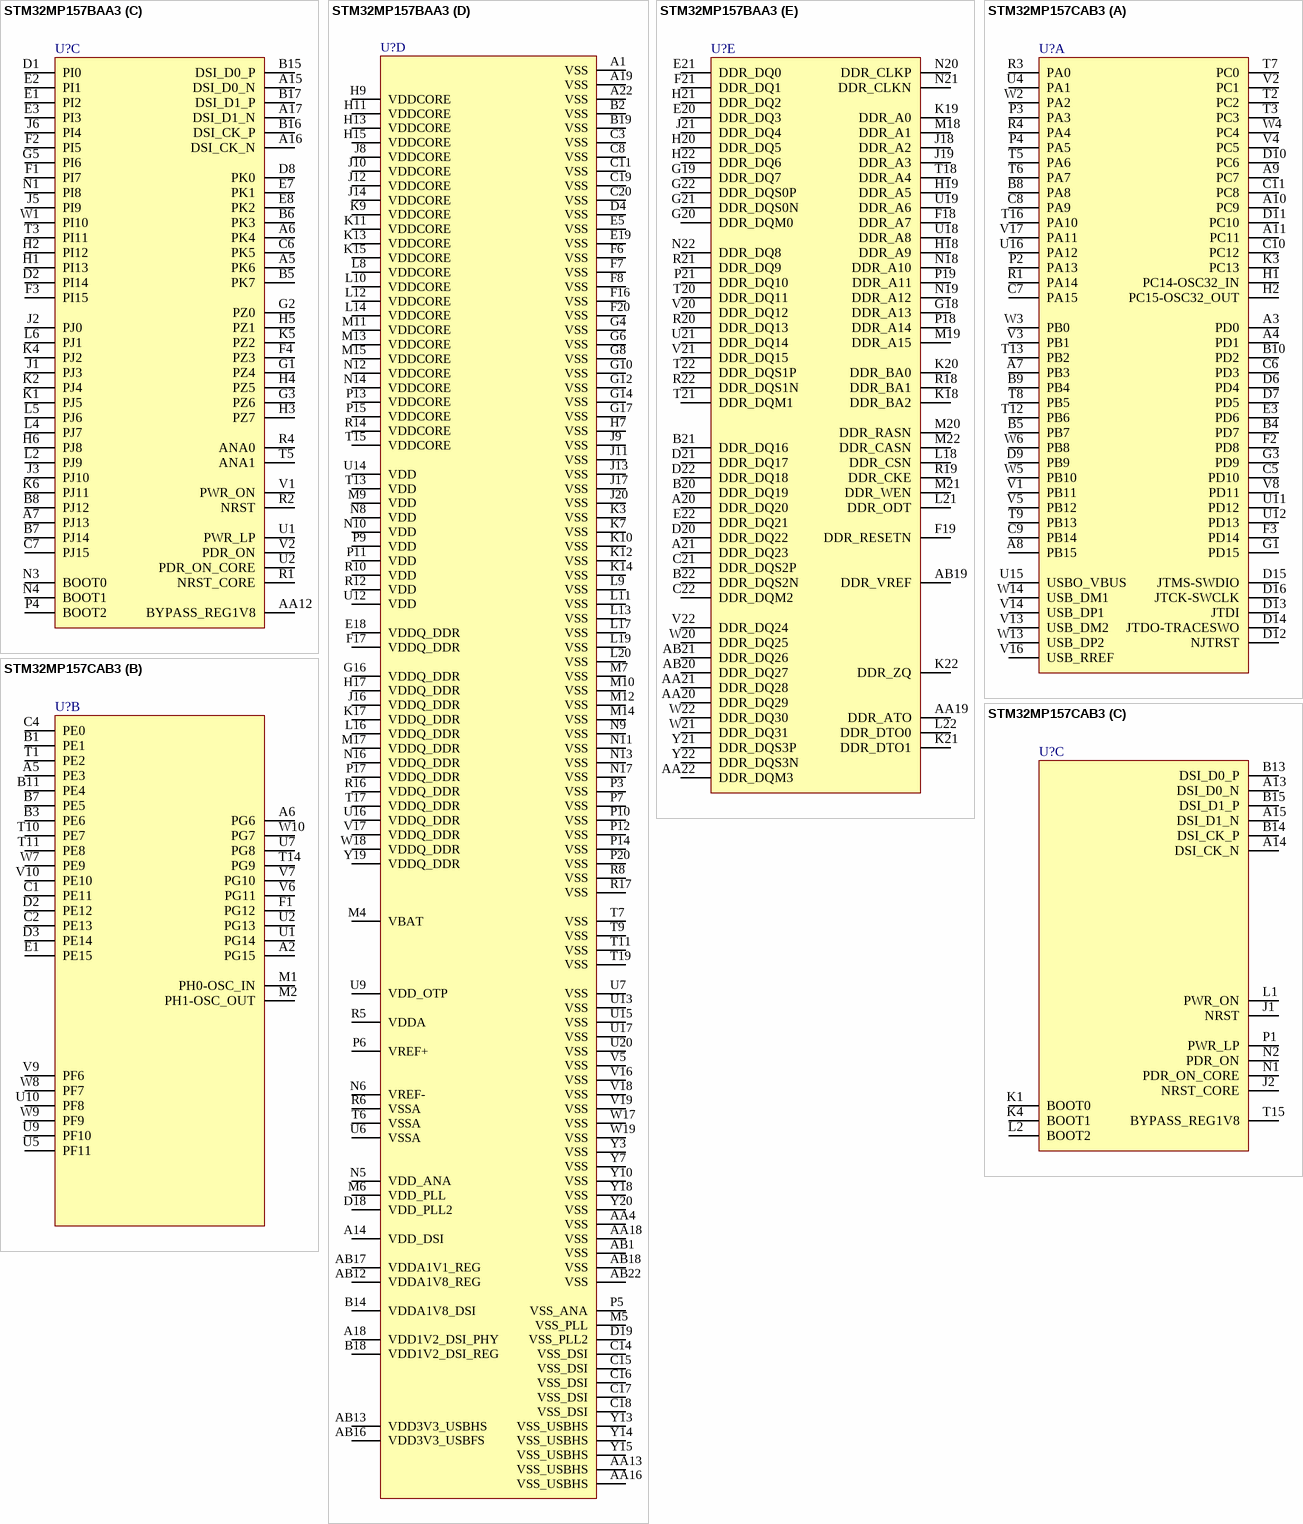
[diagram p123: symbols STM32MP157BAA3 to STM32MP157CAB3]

## STM32MP157BAA3
designator U?
part A pins: A8 PD10, A9 PD5, A11 PA9, A12 PB3, A13 PB14, AA3 PA0, AA5 PB1, AA6 PC5, AA7 PB12, AA8 PB5, AA14 USB_DM2, AA15 USB_DP1, AA17 USB_RREF, AB2 PA2, AB3 PC1, AB5 PB0, AB6 PC4, AB8 PB8, AB9 PD11, AB14 USB_DP2, AB15 USB_DM1, B10 PD1, B11 PD3, B12 PB15, B13 PA8, C9 PD4, C10 PD0, C13 PB4, D12 PD2, D13 PC7, D14 PC9, D15 PC11, D16 JTDI, D17 JTCK-SWCLK, E11 PA15, E12 PC12, E13 PC6, E14 PC8, E15 NJTRST, E16 JTDO-TRACESWO, E17 JTMS-SWDIO, F10 PD7, F11 PB7, F12 PB9, F14 PC10, L1 PD15, L3 PD6, M1 PD8, M2 PD9, M3 PD14, N2 PC13, P1 PC14-OSC32_IN, P2 PC15-OSC32_OUT, R3 PA14, T4 PA3, U3 PC3, U5 PA5, U10 PC0, V4 PA1, V6 PA4, V9 PB10, V10 PB13, V13 PB2, V14 PD13, V15 USBO_VBUS, W3 PA13, W9 PA6, W12 PD12, W13 PB6, W16 PA12, Y1 PC2, Y5 PB11, Y9 PA7, Y16 PA11, Y17 PA10
part B pins: A2 PH5, A3 PH4, A4 PE13, A10 PE3, AA1 PG13, AA2 PG14, AA9 PG10, AA10 PF7, AA11 PF6, AB4 PG4, AB7 PH2, AB10 PF8, AB11 PF9, B1 PH10, B3 PH11, B4 PE14, B9 PF1, C1 PH15, C2 PH14, C4 PE15, C5 PE0, C12 PE5, D3 PH13, D5 PE11, D6 PH8, D7 PE1, D9 PF5, D10 PG15, D11 PG6, E4 PE12, E6 PH9, E9 PE6, E10 PF0, F5 PH12, F9 PF4, F13 PF2, F15 PE4, J4 PG12, T1 PH0-OSC_IN, T2 PH1-OSC_OUT, U4 PG3, U8 PG5, U11 PG11, V3 PF3, V7 PF14, V8 PF12, V11 PH6, V12 PF10, W2 PH7, W4 PG2, W5 PG0, W6 PF15, W7 PF13, W8 PF11, W10 PE7, W11 PE9, W14 PE10, W15 PG9, Y2 PE2, Y4 PG1, Y6 PH3, Y8 PG8, Y11 PG7, Y12 PE8
part C pins: A5 PK6, A6 PK4, A7 PJ13, A15 DSI_D0_N, A16 DSI_CK_N, A17 DSI_D1_N, AA12 BYPASS_REG1V8, B5 PK7, B6 PK3, B7 PJ14, B8 PJ12, B15 DSI_D0_P, B16 DSI_CK_P, B17 DSI_D1_P, C6 PK5, C7 PJ15, D1 PI0, D2 PI14, D8 PK0, E1 PI2, E2 PI1, E3 PI3, E7 PK1, E8 PK2, F1 PI7, F2 PI5, F3 PI15, F4 PZ3, G1 PZ4, G2 PZ0, G3 PZ6, G5 PI6, H1 PI13, H2 PI12, H3 PZ7, H4 PZ5, H5 PZ1, H6 PJ8, J1 PJ3, J2 PJ0, J3 PJ10, J5 PI9, J6 PI4, K1 PJ5, K2 PJ4, K4 PJ2, K5 PZ2, K6 PJ11, L2 PJ9, L4 PJ7, L5 PJ6, L6 PJ1, N1 PI8, N3 BOOT0, N4 BOOT1, P4 BOOT2, R1 NRST_CORE, R2 NRST, R4 ANA0, T3 PI11, T5 ANA1, U1 PWR_LP, U2 PDR_ON_CORE, V1 PWR_ON, V2 PDR_ON, W1 PI10
part D pins: A1 VSS, A14 VDD_DSI, A18 VDD1V2_DSI_PHY, A19 VSS, A22 VSS, AA4 VSS, AA13 VSS_USBHS, AA16 VSS_USBHS, AA18 VSS, AB1 VSS, AB12 VDDA1V8_REG, AB13 VDD3V3_USBHS, AB16 VDD3V3_USBFS, AB17 VDDA1V1_REG, AB18 VSS, AB22 VSS, B2 VSS, B14 VDDA1V8_DSI, B18 VDD1V2_DSI_REG, B19 VSS, C3 VSS, C8 VSS, C11 VSS, C14 VSS_DSI, C15 VSS_DSI, C16 VSS_DSI, C17 VSS_DSI, C18 VSS_DSI, C19 VSS, C20 VSS, D4 VSS, D18 VDD_PLL2, D19 VSS_PLL2, E5 VSS, E18 VDDQ_DDR, E19 VSS, F6 VSS, F7 VSS, F8 VSS, F16 VSS, F17 VDDQ_DDR, F20 VSS, G4 VSS, G6 VSS, G8 VSS, G10 VSS, G12 VSS, G14 VSS, G16 VDDQ_DDR, G17 VSS, H7 VSS, H9 VDDCORE, H11 VDDCORE, H13 VDDCORE, H15 VDDCORE, H17 VDDQ_DDR, J8 VDDCORE, J9 VSS, J10 VDDCORE, J11 VSS, J12 VDDCORE, J13 VSS, J14 VDDCORE, J16 VDDQ_DDR, J17 VSS, J20 VSS, K3 VSS, K7 VSS, K9 VDDCORE, K10 VSS, K11 VDDCORE, K12 VSS, K13 VDDCORE, K14 VSS, K15 VDDCORE, K17 VDDQ_DDR, L8 VDDCORE, L9 VSS, L10 VDDCORE, L11 VSS, L12 VDDCORE, L13 VSS, L14 VDDCORE, L16 VDDQ_DDR, L17 VSS, L19 VSS, L20 VSS, M4 VBAT, M5 VSS_PLL, M6 VDD_PLL, M7 VSS, M9 VDD, M10 VSS, M11 VDDCORE, M12 VSS, M13 VDDCORE, M14 VSS, M15 VDDCORE, M17 VDDQ_DDR, N5 VDD_ANA, N6 VREF-, N8 VDD, N9 VSS, N10 VDD, N11 VSS, N12 VDDCORE, N13 VSS, N14 VDDCORE, N16 VDDQ_DDR, N17 VSS, P3 VSS, P5 VSS_ANA, P6 VREF+, P7 VSS, P9 VDD, P10 VSS, P11 VDD, P12 VSS, P13 VDDCORE, P14 VSS, P15 VDDCORE, P17 VDDQ_DDR, P20 VSS, R5 VDDA, R6 VSSA, R8 VSS, R10 VDD, R12 VDD, R14 VDDCORE, R16 VDDQ_DDR, R17 VSS, T6 VSSA, T7 VSS, T9 VSS, T11 VSS, T13 VDD, T15 VDDCORE, T17 VDDQ_DDR, T19 VSS, U6 VSSA, U7 VSS, U9 VDD_OTP, U12 VDD, U13 VSS, U14 VDD, U15 VSS, U16 VDDQ_DDR, U17 VSS, U20 VSS, V5 VSS, V16 VSS, V17 VDDQ_DDR, V18 VSS, V19 VSS, W17 VSS, W18 VDDQ_DDR, W19 VSS, Y3 VSS, Y7 VSS, Y10 VSS, Y13 VSS_USBHS, Y14 VSS_USBHS, Y15 VSS_USBHS, Y18 VSS, Y19 VDDQ_DDR, Y20 VSS
part E pins: A20 DDR_DQ20, A21 DDR_DQ23, AA19 DDR_ATO, AA20 DDR_DQ29, AA21 DDR_DQ28, AA22 DDR_DQM3, AB19 DDR_VREF, AB20 DDR_DQ27, AB21 DDR_DQ26, B20 DDR_DQ19, B21 DDR_DQ16, B22 DDR_DQS2N, C21 DDR_DQS2P, C22 DDR_DQM2, D20 DDR_DQ22, D21 DDR_DQ17, D22 DDR_DQ18, E20 DDR_DQ3, E21 DDR_DQ0, E22 DDR_DQ21, F18 DDR_A7, F19 DDR_RESETN, F21 DDR_DQ1, G18 DDR_A13, G19 DDR_DQ7, G20 DDR_DQM0, G21 DDR_DQS0N, G22 DDR_DQS0P, H18 DDR_A9, H19 DDR_A5, H20 DDR_DQ5, H21 DDR_DQ2, H22 DDR_DQ6, J18 DDR_A2, J19 DDR_A3, J21 DDR_DQ4, K18 DDR_BA2, K19 DDR_A0, K20 DDR_BA0, K21 DDR_DTO1, K22 DDR_ZQ, L18 DDR_CSN, L21 DDR_ODT, L22 DDR_DTO0, M18 DDR_A1, M19 DDR_A15, M20 DDR_RASN, M21 DDR_WEN, M22 DDR_CASN, N18 DDR_A10, N19 DDR_A12, N20 DDR_CLKP, N21 DDR_CLKN, N22 DDR_DQ8, P18 DDR_A14, P19 DDR_A11, P21 DDR_DQ10, R18 DDR_BA1, R19 DDR_CKE, R20 DDR_DQ13, R21 DDR_DQ9, R22 DDR_DQS1N, T18 DDR_A4, T20 DDR_DQ11, T21 DDR_DQM1, T22 DDR_DQS1P, U18 DDR_A8, U19 DDR_A6, U21 DDR_DQ14, V20 DDR_DQ12, V21 DDR_DQ15, V22 DDR_DQ24, W20 DDR_DQ25, W21 DDR_DQ31, W22 DDR_DQ30, Y21 DDR_DQS3P, Y22 DDR_DQS3N

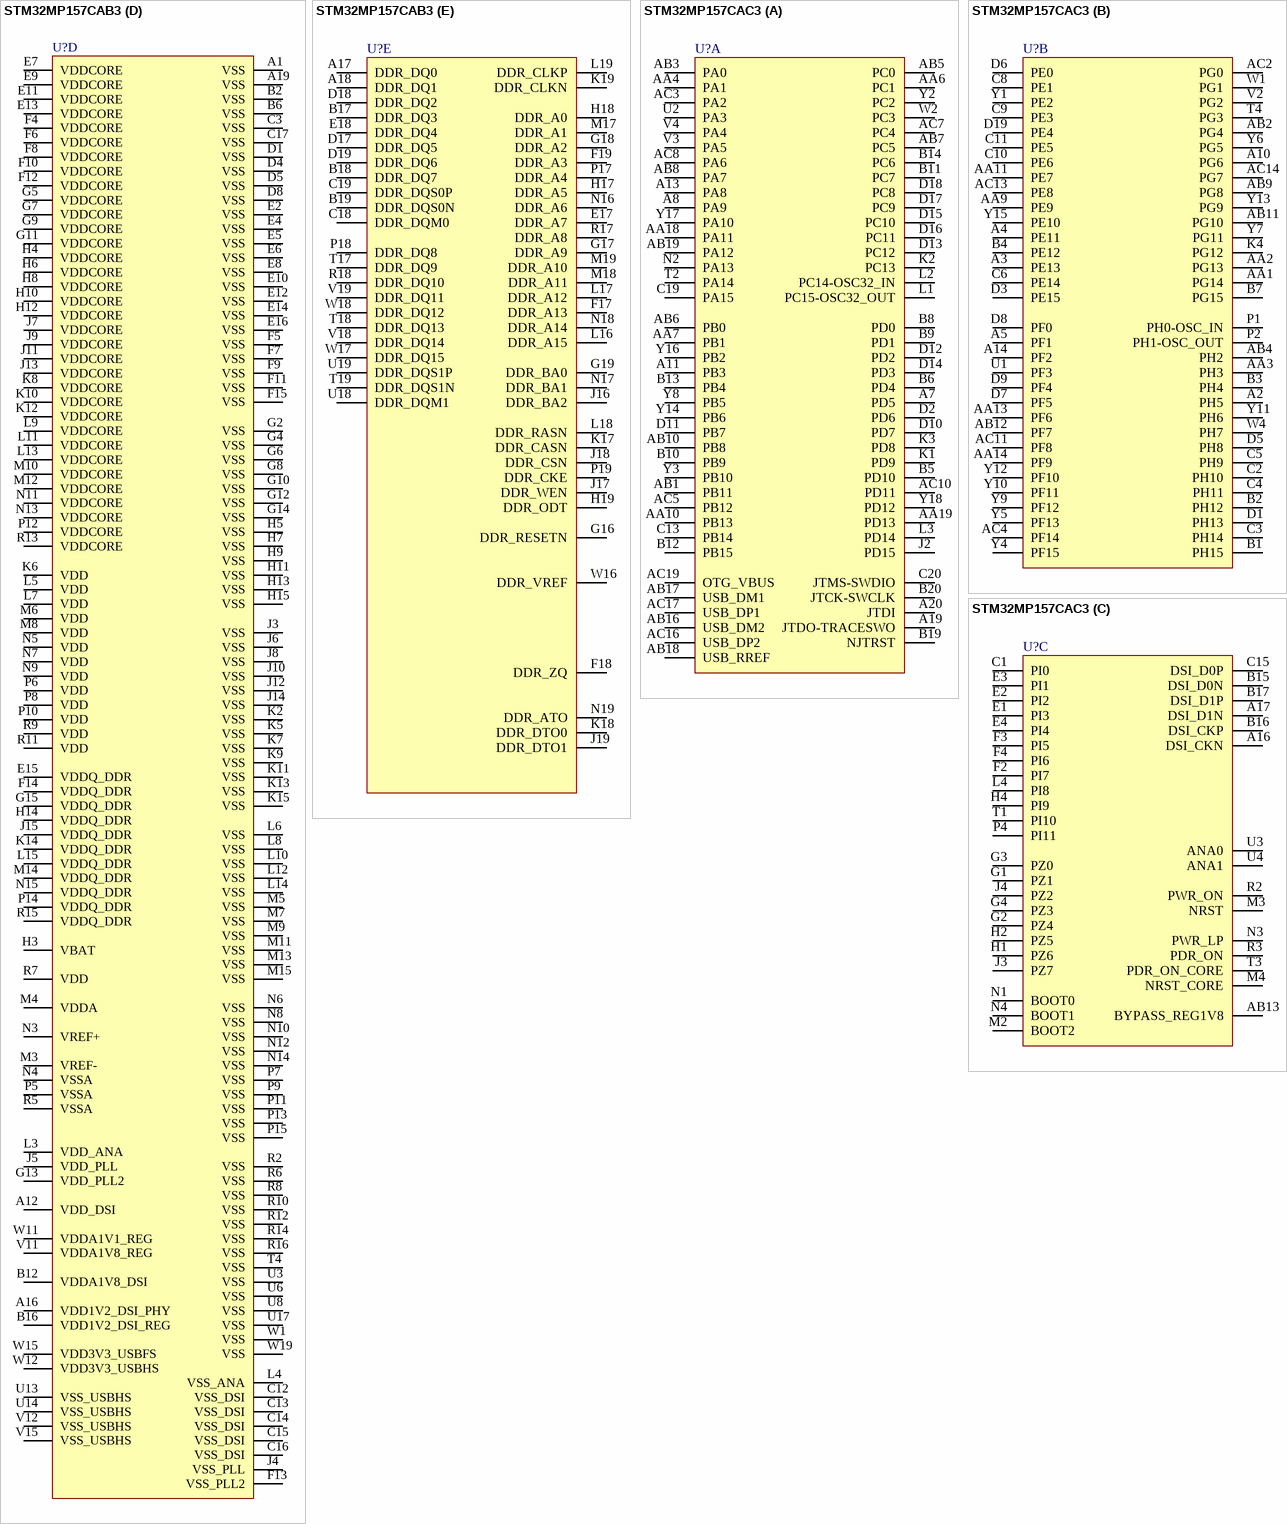
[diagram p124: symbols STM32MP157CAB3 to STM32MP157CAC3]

## STM32MP157CAB3
designator U?
part A pins: A3 PD0, A4 PD1, A7 PB3, A8 PB15, A9 PC7, A10 PC9, A11 PC11, B4 PD7, B5 PB7, B8 PA8, B9 PB4, B10 PD2, C5 PD10, C6 PD3, C7 PA15, C8 PA9, C9 PB14, C10 PC12, C11 PC8, D6 PD4, D7 PD5, D9 PB9, D10 PC6, D11 PC10, D12 NJTRST, D13 JTDI, D14 JTDO-TRACESWO, D15 JTMS-SWDIO, D16 JTCK-SWCLK, E3 PD6, F2 PD8, F3 PD14, G1 PD15, G3 PD9, H1 PC14-OSC32_IN, H2 PC15-OSC32_OUT, K3 PC13, P2 PA13, P3 PA3, P4 PA5, R1 PA14, R3 PA0, R4 PA4, T2 PC2, T3 PC3, T5 PA6, T6 PA7, T7 PC0, T8 PB5, T9 PB13, T12 PB6, T13 PB2, T16 PA10, U4 PA1, U11 PD12, U12 PD13, U15 USBO_VBUS, U16 PA12, V1 PB11, V2 PC1, V3 PB1, V4 PC5, V5 PB12, V8 PD11, V13 USB_DM2, V14 USB_DP1, V16 USB_RREF, V17 PA11, W2 PA2, W3 PB0, W4 PC4, W5 PB10, W6 PB8, W13 USB_DP2, W14 USB_DM1
part B pins: A2 PG15, A5 PE3, A6 PG6, B1 PE1, B3 PE6, B7 PE5, B11 PE4, C1 PE11, C2 PE13, C4 PE0, D2 PE12, D3 PE14, E1 PE15, F1 PG12, M1 PH0-OSC_IN, M2 PH1-OSC_OUT, T1 PE2, T10 PE7, T11 PE8, T14 PG9, U1 PG14, U2 PG13, U5 PF11, U7 PG8, U9 PF10, U10 PF8, V6 PG11, V7 PG10, V9 PF6, V10 PE10, W7 PE9, W8 PF7, W9 PF9, W10 PG7
part C pins: A13 DSI_D0_N, A14 DSI_CK_N, A15 DSI_D1_N, B13 DSI_D0_P, B14 DSI_CK_P, B15 DSI_D1_P, J1 NRST, J2 NRST_CORE, K1 BOOT0, K4 BOOT1, L1 PWR_ON, L2 BOOT2, N1 PDR_ON_CORE, N2 PDR_ON, P1 PWR_LP, T15 BYPASS_REG1V8
part D pins: A1 VSS, A12 VDD_DSI, A16 VDD1V2_DSI_PHY, A19 VSS, B2 VSS, B6 VSS, B12 VDDA1V8_DSI, B16 VDD1V2_DSI_REG, C3 VSS, C12 VSS_DSI, C13 VSS_DSI, C14 VSS_DSI, C15 VSS_DSI, C16 VSS_DSI, C17 VSS, D1 VSS, D4 VSS, D5 VSS, D8 VSS, E2 VSS, E4 VSS, E5 VSS, E6 VSS, E7 VDDCORE, E8 VSS, E9 VDDCORE, E10 VSS, E11 VDDCORE, E12 VSS, E13 VDDCORE, E14 VSS, E15 VDDQ_DDR, E16 VSS, F4 VDDCORE, F5 VSS, F6 VDDCORE, F7 VSS, F8 VDDCORE, F9 VSS, F10 VDDCORE, F11 VSS, F12 VDDCORE, F13 VSS_PLL2, F14 VDDQ_DDR, F15 VSS, G2 VSS, G4 VSS, G5 VDDCORE, G6 VSS, G7 VDDCORE, G8 VSS, G9 VDDCORE, G10 VSS, G11 VDDCORE, G12 VSS, G13 VDD_PLL2, G14 VSS, G15 VDDQ_DDR, H3 VBAT, H4 VDDCORE, H5 VSS, H6 VDDCORE, H7 VSS, H8 VDDCORE, H9 VSS, H10 VDDCORE, H11 VSS, H12 VDDCORE, H13 VSS, H14 VDDQ_DDR, H15 VSS, J3 VSS, J4 VSS_PLL, J5 VDD_PLL, J6 VSS, J7 VDDCORE, J8 VSS, J9 VDDCORE, J10 VSS, J11 VDDCORE, J12 VSS, J13 VDDCORE, J14 VSS, J15 VDDQ_DDR, K2 VSS, K5 VSS, K6 VDD, K7 VSS, K8 VDDCORE, K9 VSS, K10 VDDCORE, K11 VSS, K12 VDDCORE, K13 VSS, K14 VDDQ_DDR, K15 VSS, L3 VDD_ANA, L4 VSS_ANA, L5 VDD, L6 VSS, L7 VDD, L8 VSS, L9 VDDCORE, L10 VSS, L11 VDDCORE, L12 VSS, L13 VDDCORE, L14 VSS, L15 VDDQ_DDR, M3 VREF-, M4 VDDA, M5 VSS, M6 VDD, M7 VSS, M8 VDD, M9 VSS, M10 VDDCORE, M11 VSS, M12 VDDCORE, M13 VSS, M14 VDDQ_DDR, M15 VSS, N3 VREF+, N4 VSSA, N5 VDD, N6 VSS, N7 VDD, N8 VSS, N9 VDD, N10 VSS, N11 VDDCORE, N12 VSS, N13 VDDCORE, N14 VSS, N15 VDDQ_DDR, P5 VSSA, P6 VDD, P7 VSS, P8 VDD, P9 VSS, P10 VDD, P11 VSS, P12 VDDCORE, P13 VSS, P14 VDDQ_DDR, P15 VSS, R2 VSS, R5 VSSA, R6 VSS, R7 VDD, R8 VSS, R9 VDD, R10 VSS, R11 VDD, R12 VSS, R13 VDDCORE, R14 VSS, R15 VDDQ_DDR, R16 VSS, T4 VSS, U3 VSS, U6 VSS, U8 VSS, U13 VSS_USBHS, U14 VSS_USBHS, U17 VSS, V11 VDDA1V8_REG, V12 VSS_USBHS, V15 VSS_USBHS, W1 VSS, W11 VDDA1V1_REG, W12 VDD3V3_USBHS, W15 VDD3V3_USBFS, W19 VSS
part E pins: A17 DDR_DQ0, A18 DDR_DQ1, B17 DDR_DQ3, B18 DDR_DQ7, B19 DDR_DQS0N, C18 DDR_DQM0, C19 DDR_DQS0P, D17 DDR_DQ5, D18 DDR_DQ2, D19 DDR_DQ6, E17 DDR_A7, E18 DDR_DQ4, F17 DDR_A13, F18 DDR_ZQ, F19 DDR_A3, G16 DDR_RESETN, G17 DDR_A9, G18 DDR_A2, G19 DDR_BA0, H17 DDR_A5, H18 DDR_A0, H19 DDR_ODT, J16 DDR_BA2, J17 DDR_WEN, J18 DDR_CSN, J19 DDR_DTO1, K17 DDR_CASN, K18 DDR_DTO0, K19 DDR_CLKN, L16 DDR_A15, L17 DDR_A12, L18 DDR_RASN, L19 DDR_CLKP, M17 DDR_A1, M18 DDR_A11, M19 DDR_A10, N16 DDR_A6, N17 DDR_BA1, N18 DDR_A14, N19 DDR_ATO, P17 DDR_A4, P18 DDR_DQ8, P19 DDR_CKE, R17 DDR_A8, R18 DDR_DQ10, T17 DDR_DQ9, T18 DDR_DQ13, T19 DDR_DQS1N, U18 DDR_DQM1, U19 DDR_DQS1P, V18 DDR_DQ14, V19 DDR_DQ11, W16 DDR_VREF, W17 DDR_DQ15, W18 DDR_DQ12

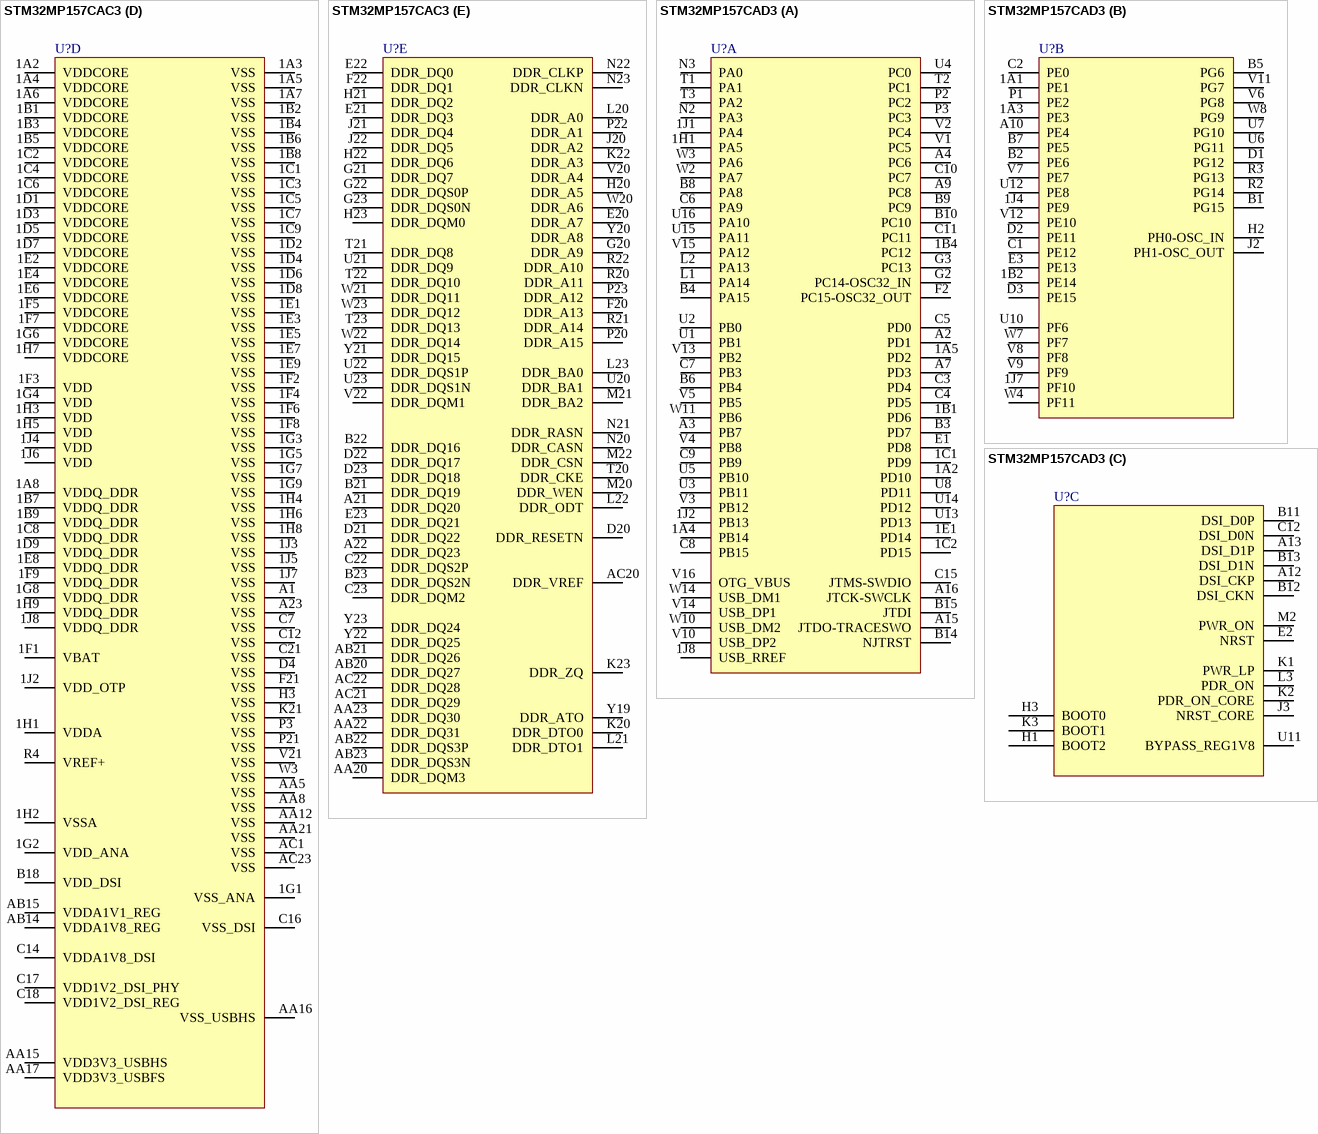
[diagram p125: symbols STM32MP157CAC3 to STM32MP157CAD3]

## STM32MP157CAC3
designator U?
part A pins: A7 PD5, A8 PA9, A11 PB3, A13 PA8, A19 JTDO-TRACESWO, A20 JTDI, AA4 PA1, AA6 PC1, AA7 PB1, AA10 PB13, AA18 PA11, AA19 PD13, AB1 PB11, AB3 PA0, AB5 PC0, AB6 PB0, AB7 PC5, AB8 PA7, AB10 PB8, AB16 USB_DM2, AB17 USB_DM1, AB18 USB_RREF, AB19 PA12, AC3 PA2, AC5 PB12, AC7 PC4, AC8 PA6, AC10 PD11, AC16 USB_DP2, AC17 USB_DP1, AC19 OTG_VBUS, B5 PD10, B6 PD4, B8 PD0, B9 PD1, B10 PB9, B11 PC7, B12 PB15, B13 PB4, B14 PC6, B19 NJTRST, B20 JTCK-SWCLK, C13 PB14, C19 PA15, C20 JTMS-SWDIO, D2 PD6, D10 PD7, D11 PB7, D12 PD2, D13 PC12, D14 PD3, D15 PC10, D16 PC11, D17 PC9, D18 PC8, J2 PD15, K1 PD9, K2 PC13, K3 PD8, L1 PC15-OSC32_OUT, L2 PC14-OSC32_IN, L3 PD14, N2 PA13, T2 PA14, U2 PA3, V3 PA5, V4 PA4, W2 PC3, Y2 PC2, Y3 PB10, Y8 PB5, Y14 PB6, Y16 PB2, Y17 PA10, Y18 PD12
part B pins: A2 PH5, A3 PE13, A4 PE11, A5 PF1, A10 PG6, A14 PF2, AA1 PG14, AA2 PG13, AA3 PH3, AA9 PE9, AA11 PE7, AA13 PF6, AA14 PF9, AB2 PG4, AB4 PH2, AB9 PG8, AB11 PG10, AB12 PF7, AC2 PG0, AC4 PF14, AC11 PF8, AC13 PE8, AC14 PG7, B1 PH15, B2 PH12, B3 PH4, B4 PE12, B7 PG15, C2 PH10, C3 PH14, C4 PH11, C5 PH9, C6 PE14, C8 PE1, C9 PE3, C10 PE6, C11 PE5, D1 PH13, D3 PE15, D5 PH8, D6 PE0, D7 PF5, D8 PF0, D9 PF4, D19 PE4, K4 PG12, P1 PH0-OSC_IN, P2 PH1-OSC_OUT, T4 PG3, U1 PF3, V2 PG2, W1 PG1, W4 PH7, Y1 PE2, Y4 PF15, Y5 PF13, Y6 PG5, Y7 PG11, Y9 PF12, Y10 PF11, Y11 PH6, Y12 PF10, Y13 PG9, Y15 PE10
part C pins: A16 DSI_CKN, A17 DSI_D1N, AB13 BYPASS_REG1V8, B15 DSI_D0N, B16 DSI_CKP, B17 DSI_D1P, C1 PI0, C15 DSI_D0P, E1 PI3, E2 PI2, E3 PI1, E4 PI4, F2 PI7, F3 PI5, F4 PI6, G1 PZ1, G2 PZ4, G3 PZ0, G4 PZ3, H1 PZ6, H2 PZ5, H4 PI9, J3 PZ7, J4 PZ2, L4 PI8, M2 BOOT2, M3 NRST, M4 NRST_CORE, N1 BOOT0, N3 PWR_LP, N4 BOOT1, P4 PI11, R2 PWR_ON, R3 PDR_ON, T1 PI10, T3 PDR_ON_CORE, U3 ANA0, U4 ANA1
part D pins: 1A2 VDDCORE, 1A3 VSS, 1A4 VDDCORE, 1A5 VSS, 1A6 VDDCORE, 1A7 VSS, 1A8 VDDQ_DDR, 1B1 VDDCORE, 1B2 VSS, 1B3 VDDCORE, 1B4 VSS, 1B5 VDDCORE, 1B6 VSS, 1B7 VDDQ_DDR, 1B8 VSS, 1B9 VDDQ_DDR, 1C1 VSS, 1C2 VDDCORE, 1C3 VSS, 1C4 VDDCORE, 1C5 VSS, 1C6 VDDCORE, 1C7 VSS, 1C8 VDDQ_DDR, 1C9 VSS, 1D1 VDDCORE, 1D2 VSS, 1D3 VDDCORE, 1D4 VSS, 1D5 VDDCORE, 1D6 VSS, 1D7 VDDCORE, 1D8 VSS, 1D9 VDDQ_DDR, 1E1 VSS, 1E2 VDDCORE, 1E3 VSS, 1E4 VDDCORE, 1E5 VSS, 1E6 VDDCORE, 1E7 VSS, 1E8 VDDQ_DDR, 1E9 VSS, 1F1 VBAT, 1F2 VSS, 1F3 VDD, 1F4 VSS, 1F5 VDDCORE, 1F6 VSS, 1F7 VDDCORE, 1F8 VSS, 1F9 VDDQ_DDR, 1G1 VSS_ANA, 1G2 VDD_ANA, 1G3 VSS, 1G4 VDD, 1G5 VSS, 1G6 VDDCORE, 1G7 VSS, 1G8 VDDQ_DDR, 1G9 VSS, 1H1 VDDA, 1H2 VSSA, 1H3 VDD, 1H4 VSS, 1H5 VDD, 1H6 VSS, 1H7 VDDCORE, 1H8 VSS, 1H9 VDDQ_DDR, 1J2 VDD_OTP, 1J3 VSS, 1J4 VDD, 1J5 VSS, 1J6 VDD, 1J7 VSS, 1J8 VDDQ_DDR, A1 VSS, A23 VSS, AA5 VSS, AA8 VSS, AA12 VSS, AA15 VDD3V3_USBHS, AA16 VSS_USBHS, AA17 VDD3V3_USBFS, AA21 VSS, AB14 VDDA1V8_REG, AB15 VDDA1V1_REG, AC1 VSS, AC23 VSS, B18 VDD_DSI, C7 VSS, C12 VSS, C14 VDDA1V8_DSI, C16 VSS_DSI, C17 VDD1V2_DSI_PHY, C18 VDD1V2_DSI_REG, C21 VSS, D4 VSS, F21 VSS, H3 VSS, K21 VSS, P3 VSS, P21 VSS, R4 VREF+, V21 VSS, W3 VSS
part E pins: A21 DDR_DQ20, A22 DDR_DQ23, AA20 DDR_DQM3, AA22 DDR_DQ31, AA23 DDR_DQ30, AB20 DDR_DQ27, AB21 DDR_DQ26, AB22 DDR_DQS3P, AB23 DDR_DQS3N, AC20 DDR_VREF, AC21 DDR_DQ29, AC22 DDR_DQ28, B21 DDR_DQ19, B22 DDR_DQ16, B23 DDR_DQS2N, C22 DDR_DQS2P, C23 DDR_DQM2, D20 DDR_RESETN, D21 DDR_DQ22, D22 DDR_DQ17, D23 DDR_DQ18, E20 DDR_A7, E21 DDR_DQ3, E22 DDR_DQ0, E23 DDR_DQ21, F20 DDR_A13, F22 DDR_DQ1, G20 DDR_A9, G21 DDR_DQ7, G22 DDR_DQS0P, G23 DDR_DQS0N, H20 DDR_A5, H21 DDR_DQ2, H22 DDR_DQ6, H23 DDR_DQM0, J20 DDR_A2, J21 DDR_DQ4, J22 DDR_DQ5, K20 DDR_DTO0, K22 DDR_A3, K23 DDR_ZQ, L20 DDR_A0, L21 DDR_DTO1, L22 DDR_ODT, L23 DDR_BA0, M20 DDR_WEN, M21 DDR_BA2, M22 DDR_CSN, N20 DDR_CASN, N21 DDR_RASN, N22 DDR_CLKP, N23 DDR_CLKN, P20 DDR_A15, P22 DDR_A1, P23 DDR_A12, R20 DDR_A11, R21 DDR_A14, R22 DDR_A10, T20 DDR_CKE, T21 DDR_DQ8, T22 DDR_DQ10, T23 DDR_DQ13, U20 DDR_BA1, U21 DDR_DQ9, U22 DDR_DQS1P, U23 DDR_DQS1N, V20 DDR_A4, V22 DDR_DQM1, W20 DDR_A6, W21 DDR_DQ11, W22 DDR_DQ14, W23 DDR_DQ12, Y19 DDR_ATO, Y20 DDR_A8, Y21 DDR_DQ15, Y22 DDR_DQ25, Y23 DDR_DQ24

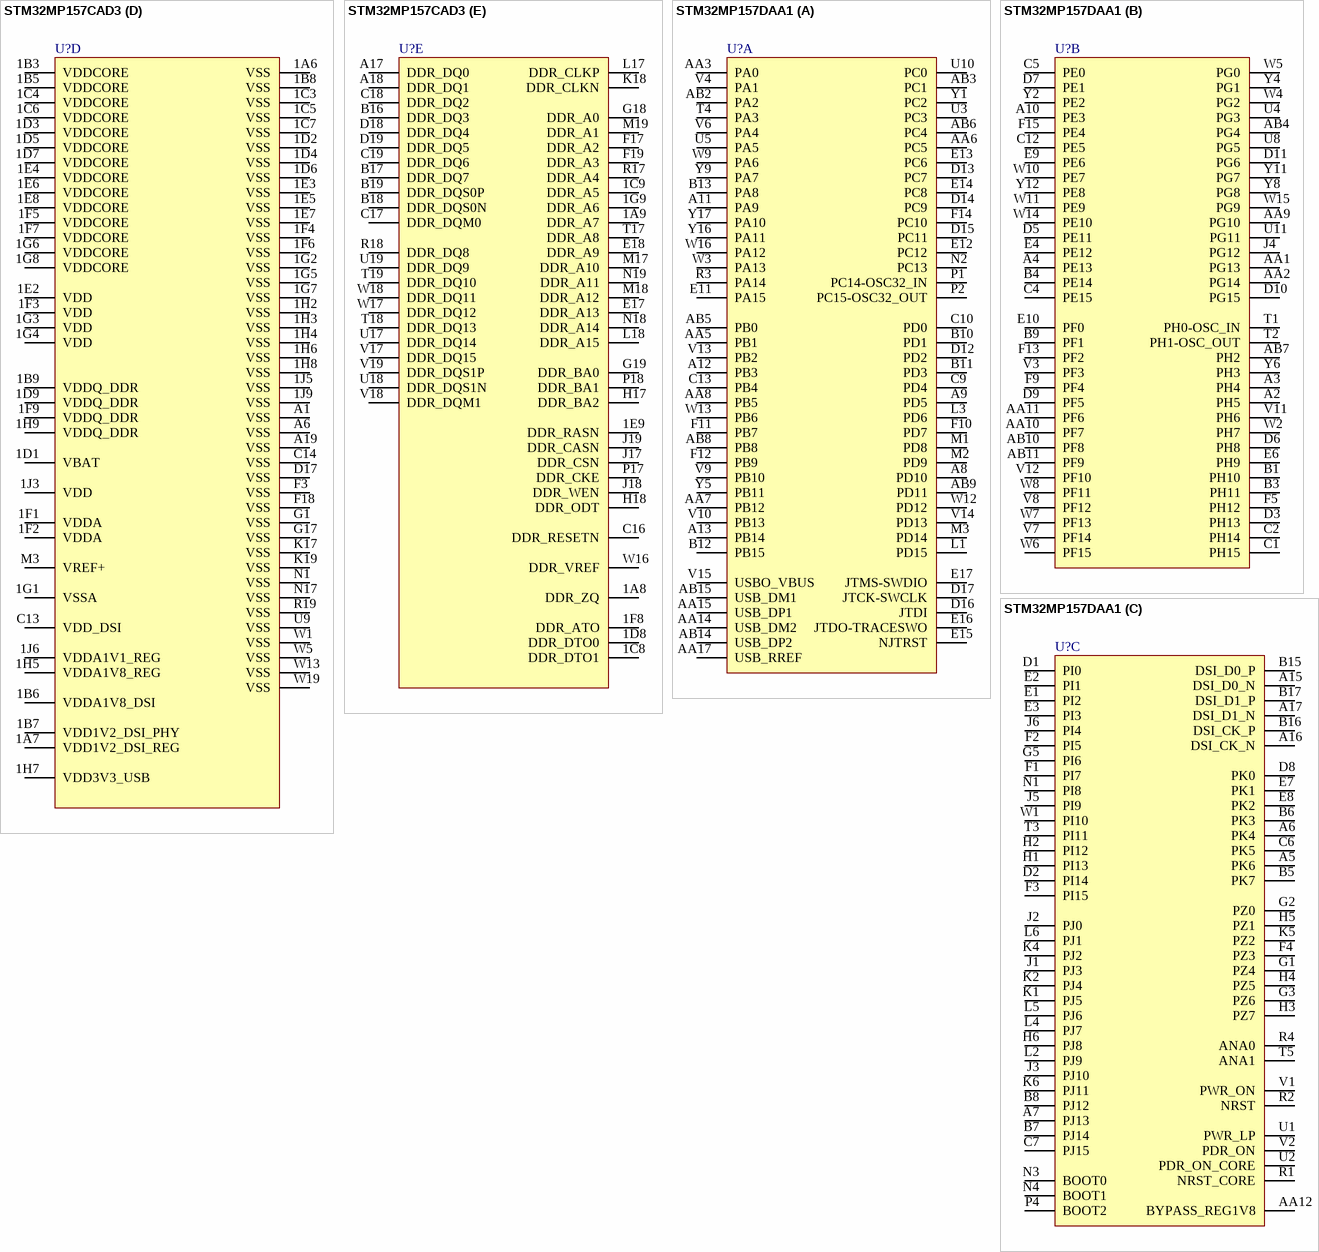
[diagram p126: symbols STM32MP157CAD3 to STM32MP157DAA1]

## STM32MP157CAD3
designator U?
part A pins: 1A2 PD10, 1A4 PB14, 1A5 PD2, 1B1 PD6, 1B4 PC12, 1C1 PD9, 1C2 PD15, 1E1 PD14, 1H1 PA5, 1J1 PA4, 1J2 PB13, 1J8 USB_RREF, A2 PD1, A3 PB7, A4 PC6, A7 PD3, A9 PC8, A15 JTDO-TRACESWO, A16 JTCK-SWCLK, B3 PD7, B4 PA15, B6 PB4, B8 PA8, B9 PC9, B10 PC10, B14 NJTRST, B15 JTDI, C3 PD4, C4 PD5, C5 PD0, C6 PA9, C7 PB3, C8 PB15, C9 PB9, C10 PC7, C11 PC11, C15 JTMS-SWDIO, E1 PD8, F2 PC15-OSC32_OUT, G2 PC14-OSC32_IN, G3 PC13, L1 PA14, L2 PA13, N2 PA3, N3 PA0, P2 PC2, P3 PC3, T1 PA1, T2 PC1, T3 PA2, U1 PB1, U2 PB0, U3 PB11, U4 PC0, U5 PB10, U8 PD11, U13 PD13, U14 PD12, U15 PA11, U16 PA10, V1 PC5, V2 PC4, V3 PB12, V4 PB8, V5 PB5, V10 USB_DP2, V13 PB2, V14 USB_DP1, V15 PA12, V16 OTG_VBUS, W2 PA7, W3 PA6, W10 USB_DM2, W11 PB6, W14 USB_DM1
part B pins: 1A1 PE1, 1A3 PE3, 1B2 PE14, 1J4 PE9, 1J7 PF10, A10 PE4, B1 PG15, B2 PE6, B5 PG6, B7 PE5, C1 PE12, C2 PE0, D1 PG12, D2 PE11, D3 PE15, E3 PE13, H2 PH0-OSC_IN, J2 PH1-OSC_OUT, P1 PE2, R2 PG14, R3 PG13, U6 PG11, U7 PG10, U10 PF6, U12 PE8, V6 PG8, V7 PE7, V8 PF8, V9 PF9, V11 PG7, V12 PE10, W4 PF11, W7 PF7, W8 PG9
part C pins: A12 DSI_CKP, A13 DSI_D1P, B11 DSI_D0P, B12 DSI_CKN, B13 DSI_D1N, C12 DSI_D0N, E2 NRST, H1 BOOT2, H3 BOOT0, J3 NRST_CORE, K1 PWR_LP, K2 PDR_ON_CORE, K3 BOOT1, L3 PDR_ON, M2 PWR_ON, U11 BYPASS_REG1V8
part D pins: 1A6 VSS, 1A7 VDD1V2_DSI_REG, 1B3 VDDCORE, 1B5 VDDCORE, 1B6 VDDA1V8_DSI, 1B7 VDD1V2_DSI_PHY, 1B8 VSS, 1B9 VDDQ_DDR, 1C3 VSS, 1C4 VDDCORE, 1C5 VSS, 1C6 VDDCORE, 1C7 VSS, 1D1 VBAT, 1D2 VSS, 1D3 VDDCORE, 1D4 VSS, 1D5 VDDCORE, 1D6 VSS, 1D7 VDDCORE, 1D9 VDDQ_DDR, 1E2 VDD, 1E3 VSS, 1E4 VDDCORE, 1E5 VSS, 1E6 VDDCORE, 1E7 VSS, 1E8 VDDCORE, 1F1 VDDA, 1F2 VDDA, 1F3 VDD, 1F4 VSS, 1F5 VDDCORE, 1F6 VSS, 1F7 VDDCORE, 1F9 VDDQ_DDR, 1G1 VSSA, 1G2 VSS, 1G3 VDD, 1G4 VDD, 1G5 VSS, 1G6 VDDCORE, 1G7 VSS, 1G8 VDDCORE, 1H2 VSS, 1H3 VSS, 1H4 VSS, 1H5 VDDA1V8_REG, 1H6 VSS, 1H7 VDD3V3_USB, 1H8 VSS, 1H9 VDDQ_DDR, 1J3 VDD, 1J5 VSS, 1J6 VDDA1V1_REG, 1J9 VSS, A1 VSS, A6 VSS, A19 VSS, C13 VDD_DSI, C14 VSS, D17 VSS, F3 VSS, F18 VSS, G1 VSS, G17 VSS, K17 VSS, K19 VSS, M3 VREF+, N1 VSS, N17 VSS, R19 VSS, U9 VSS, W1 VSS, W5 VSS, W13 VSS, W19 VSS
part E pins: 1A8 DDR_ZQ, 1A9 DDR_A7, 1C8 DDR_DTO1, 1C9 DDR_A5, 1D8 DDR_DTO0, 1E9 DDR_RASN, 1F8 DDR_ATO, 1G9 DDR_A6, A17 DDR_DQ0, A18 DDR_DQ1, B16 DDR_DQ3, B17 DDR_DQ7, B18 DDR_DQS0N, B19 DDR_DQS0P, C16 DDR_RESETN, C17 DDR_DQM0, C18 DDR_DQ2, C19 DDR_DQ6, D18 DDR_DQ4, D19 DDR_DQ5, E17 DDR_A13, E18 DDR_A9, F17 DDR_A2, F19 DDR_A3, G18 DDR_A0, G19 DDR_BA0, H17 DDR_BA2, H18 DDR_ODT, J17 DDR_CSN, J18 DDR_WEN, J19 DDR_CASN, K18 DDR_CLKN, L17 DDR_CLKP, L18 DDR_A15, M17 DDR_A10, M18 DDR_A12, M19 DDR_A1, N18 DDR_A14, N19 DDR_A11, P17 DDR_CKE, P18 DDR_BA1, R17 DDR_A4, R18 DDR_DQ8, T17 DDR_A8, T18 DDR_DQ13, T19 DDR_DQ10, U17 DDR_DQ14, U18 DDR_DQS1N, U19 DDR_DQ9, V17 DDR_DQ15, V18 DDR_DQM1, V19 DDR_DQS1P, W16 DDR_VREF, W17 DDR_DQ12, W18 DDR_DQ11

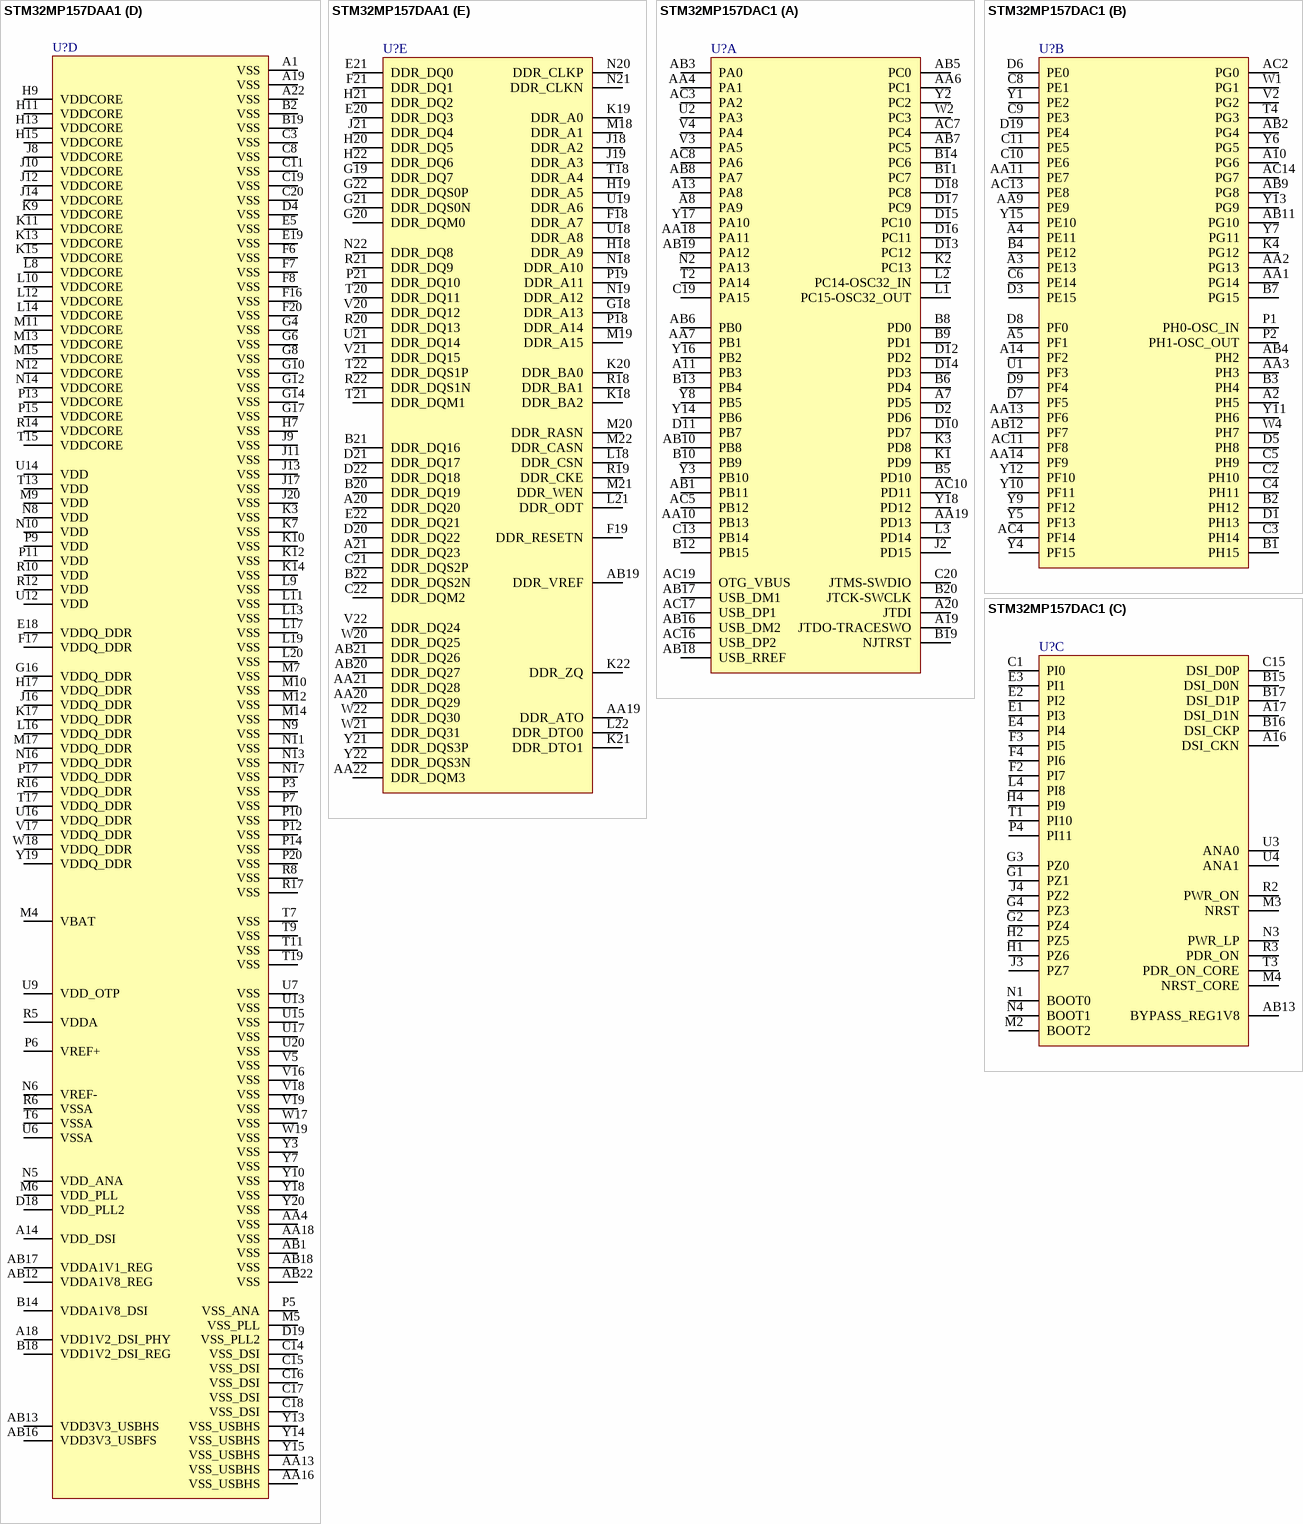
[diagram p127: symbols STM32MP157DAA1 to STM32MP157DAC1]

## STM32MP157DAA1
designator U?
part A pins: A8 PD10, A9 PD5, A11 PA9, A12 PB3, A13 PB14, AA3 PA0, AA5 PB1, AA6 PC5, AA7 PB12, AA8 PB5, AA14 USB_DM2, AA15 USB_DP1, AA17 USB_RREF, AB2 PA2, AB3 PC1, AB5 PB0, AB6 PC4, AB8 PB8, AB9 PD11, AB14 USB_DP2, AB15 USB_DM1, B10 PD1, B11 PD3, B12 PB15, B13 PA8, C9 PD4, C10 PD0, C13 PB4, D12 PD2, D13 PC7, D14 PC9, D15 PC11, D16 JTDI, D17 JTCK-SWCLK, E11 PA15, E12 PC12, E13 PC6, E14 PC8, E15 NJTRST, E16 JTDO-TRACESWO, E17 JTMS-SWDIO, F10 PD7, F11 PB7, F12 PB9, F14 PC10, L1 PD15, L3 PD6, M1 PD8, M2 PD9, M3 PD14, N2 PC13, P1 PC14-OSC32_IN, P2 PC15-OSC32_OUT, R3 PA14, T4 PA3, U3 PC3, U5 PA5, U10 PC0, V4 PA1, V6 PA4, V9 PB10, V10 PB13, V13 PB2, V14 PD13, V15 USBO_VBUS, W3 PA13, W9 PA6, W12 PD12, W13 PB6, W16 PA12, Y1 PC2, Y5 PB11, Y9 PA7, Y16 PA11, Y17 PA10
part B pins: A2 PH5, A3 PH4, A4 PE13, A10 PE3, AA1 PG13, AA2 PG14, AA9 PG10, AA10 PF7, AA11 PF6, AB4 PG4, AB7 PH2, AB10 PF8, AB11 PF9, B1 PH10, B3 PH11, B4 PE14, B9 PF1, C1 PH15, C2 PH14, C4 PE15, C5 PE0, C12 PE5, D3 PH13, D5 PE11, D6 PH8, D7 PE1, D9 PF5, D10 PG15, D11 PG6, E4 PE12, E6 PH9, E9 PE6, E10 PF0, F5 PH12, F9 PF4, F13 PF2, F15 PE4, J4 PG12, T1 PH0-OSC_IN, T2 PH1-OSC_OUT, U4 PG3, U8 PG5, U11 PG11, V3 PF3, V7 PF14, V8 PF12, V11 PH6, V12 PF10, W2 PH7, W4 PG2, W5 PG0, W6 PF15, W7 PF13, W8 PF11, W10 PE7, W11 PE9, W14 PE10, W15 PG9, Y2 PE2, Y4 PG1, Y6 PH3, Y8 PG8, Y11 PG7, Y12 PE8
part C pins: A5 PK6, A6 PK4, A7 PJ13, A15 DSI_D0_N, A16 DSI_CK_N, A17 DSI_D1_N, AA12 BYPASS_REG1V8, B5 PK7, B6 PK3, B7 PJ14, B8 PJ12, B15 DSI_D0_P, B16 DSI_CK_P, B17 DSI_D1_P, C6 PK5, C7 PJ15, D1 PI0, D2 PI14, D8 PK0, E1 PI2, E2 PI1, E3 PI3, E7 PK1, E8 PK2, F1 PI7, F2 PI5, F3 PI15, F4 PZ3, G1 PZ4, G2 PZ0, G3 PZ6, G5 PI6, H1 PI13, H2 PI12, H3 PZ7, H4 PZ5, H5 PZ1, H6 PJ8, J1 PJ3, J2 PJ0, J3 PJ10, J5 PI9, J6 PI4, K1 PJ5, K2 PJ4, K4 PJ2, K5 PZ2, K6 PJ11, L2 PJ9, L4 PJ7, L5 PJ6, L6 PJ1, N1 PI8, N3 BOOT0, N4 BOOT1, P4 BOOT2, R1 NRST_CORE, R2 NRST, R4 ANA0, T3 PI11, T5 ANA1, U1 PWR_LP, U2 PDR_ON_CORE, V1 PWR_ON, V2 PDR_ON, W1 PI10
part D pins: A1 VSS, A14 VDD_DSI, A18 VDD1V2_DSI_PHY, A19 VSS, A22 VSS, AA4 VSS, AA13 VSS_USBHS, AA16 VSS_USBHS, AA18 VSS, AB1 VSS, AB12 VDDA1V8_REG, AB13 VDD3V3_USBHS, AB16 VDD3V3_USBFS, AB17 VDDA1V1_REG, AB18 VSS, AB22 VSS, B2 VSS, B14 VDDA1V8_DSI, B18 VDD1V2_DSI_REG, B19 VSS, C3 VSS, C8 VSS, C11 VSS, C14 VSS_DSI, C15 VSS_DSI, C16 VSS_DSI, C17 VSS_DSI, C18 VSS_DSI, C19 VSS, C20 VSS, D4 VSS, D18 VDD_PLL2, D19 VSS_PLL2, E5 VSS, E18 VDDQ_DDR, E19 VSS, F6 VSS, F7 VSS, F8 VSS, F16 VSS, F17 VDDQ_DDR, F20 VSS, G4 VSS, G6 VSS, G8 VSS, G10 VSS, G12 VSS, G14 VSS, G16 VDDQ_DDR, G17 VSS, H7 VSS, H9 VDDCORE, H11 VDDCORE, H13 VDDCORE, H15 VDDCORE, H17 VDDQ_DDR, J8 VDDCORE, J9 VSS, J10 VDDCORE, J11 VSS, J12 VDDCORE, J13 VSS, J14 VDDCORE, J16 VDDQ_DDR, J17 VSS, J20 VSS, K3 VSS, K7 VSS, K9 VDDCORE, K10 VSS, K11 VDDCORE, K12 VSS, K13 VDDCORE, K14 VSS, K15 VDDCORE, K17 VDDQ_DDR, L8 VDDCORE, L9 VSS, L10 VDDCORE, L11 VSS, L12 VDDCORE, L13 VSS, L14 VDDCORE, L16 VDDQ_DDR, L17 VSS, L19 VSS, L20 VSS, M4 VBAT, M5 VSS_PLL, M6 VDD_PLL, M7 VSS, M9 VDD, M10 VSS, M11 VDDCORE, M12 VSS, M13 VDDCORE, M14 VSS, M15 VDDCORE, M17 VDDQ_DDR, N5 VDD_ANA, N6 VREF-, N8 VDD, N9 VSS, N10 VDD, N11 VSS, N12 VDDCORE, N13 VSS, N14 VDDCORE, N16 VDDQ_DDR, N17 VSS, P3 VSS, P5 VSS_ANA, P6 VREF+, P7 VSS, P9 VDD, P10 VSS, P11 VDD, P12 VSS, P13 VDDCORE, P14 VSS, P15 VDDCORE, P17 VDDQ_DDR, P20 VSS, R5 VDDA, R6 VSSA, R8 VSS, R10 VDD, R12 VDD, R14 VDDCORE, R16 VDDQ_DDR, R17 VSS, T6 VSSA, T7 VSS, T9 VSS, T11 VSS, T13 VDD, T15 VDDCORE, T17 VDDQ_DDR, T19 VSS, U6 VSSA, U7 VSS, U9 VDD_OTP, U12 VDD, U13 VSS, U14 VDD, U15 VSS, U16 VDDQ_DDR, U17 VSS, U20 VSS, V5 VSS, V16 VSS, V17 VDDQ_DDR, V18 VSS, V19 VSS, W17 VSS, W18 VDDQ_DDR, W19 VSS, Y3 VSS, Y7 VSS, Y10 VSS, Y13 VSS_USBHS, Y14 VSS_USBHS, Y15 VSS_USBHS, Y18 VSS, Y19 VDDQ_DDR, Y20 VSS
part E pins: A20 DDR_DQ20, A21 DDR_DQ23, AA19 DDR_ATO, AA20 DDR_DQ29, AA21 DDR_DQ28, AA22 DDR_DQM3, AB19 DDR_VREF, AB20 DDR_DQ27, AB21 DDR_DQ26, B20 DDR_DQ19, B21 DDR_DQ16, B22 DDR_DQS2N, C21 DDR_DQS2P, C22 DDR_DQM2, D20 DDR_DQ22, D21 DDR_DQ17, D22 DDR_DQ18, E20 DDR_DQ3, E21 DDR_DQ0, E22 DDR_DQ21, F18 DDR_A7, F19 DDR_RESETN, F21 DDR_DQ1, G18 DDR_A13, G19 DDR_DQ7, G20 DDR_DQM0, G21 DDR_DQS0N, G22 DDR_DQS0P, H18 DDR_A9, H19 DDR_A5, H20 DDR_DQ5, H21 DDR_DQ2, H22 DDR_DQ6, J18 DDR_A2, J19 DDR_A3, J21 DDR_DQ4, K18 DDR_BA2, K19 DDR_A0, K20 DDR_BA0, K21 DDR_DTO1, K22 DDR_ZQ, L18 DDR_CSN, L21 DDR_ODT, L22 DDR_DTO0, M18 DDR_A1, M19 DDR_A15, M20 DDR_RASN, M21 DDR_WEN, M22 DDR_CASN, N18 DDR_A10, N19 DDR_A12, N20 DDR_CLKP, N21 DDR_CLKN, N22 DDR_DQ8, P18 DDR_A14, P19 DDR_A11, P21 DDR_DQ10, R18 DDR_BA1, R19 DDR_CKE, R20 DDR_DQ13, R21 DDR_DQ9, R22 DDR_DQS1N, T18 DDR_A4, T20 DDR_DQ11, T21 DDR_DQM1, T22 DDR_DQS1P, U18 DDR_A8, U19 DDR_A6, U21 DDR_DQ14, V20 DDR_DQ12, V21 DDR_DQ15, V22 DDR_DQ24, W20 DDR_DQ25, W21 DDR_DQ31, W22 DDR_DQ30, Y21 DDR_DQS3P, Y22 DDR_DQS3N

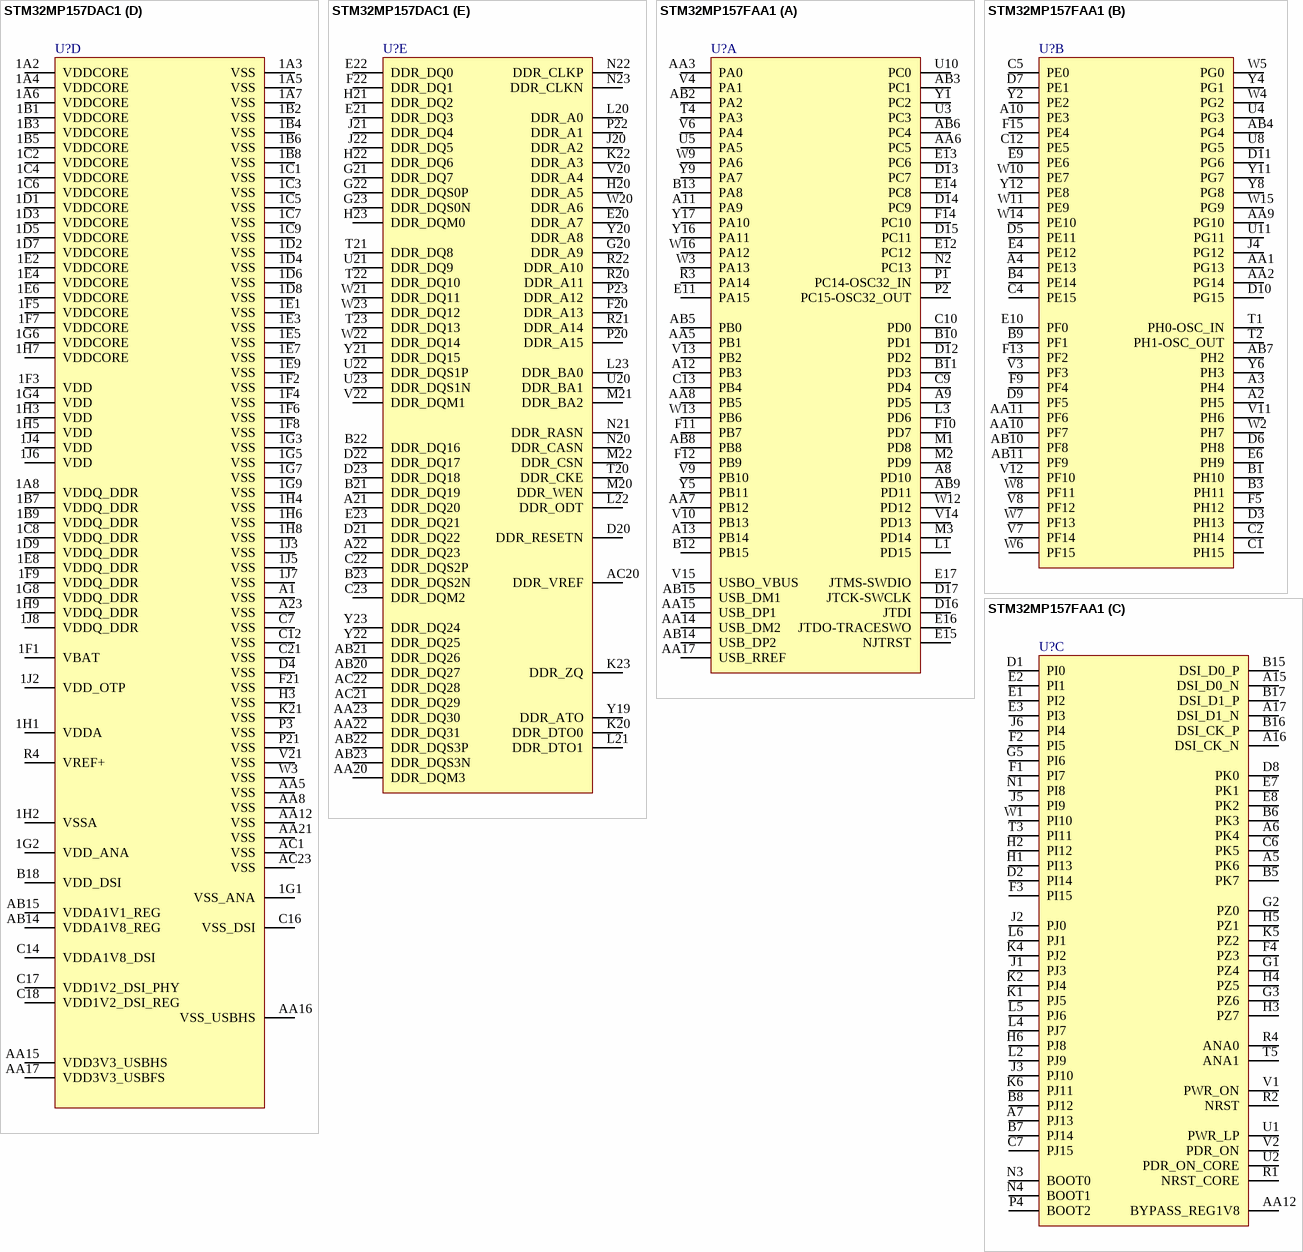
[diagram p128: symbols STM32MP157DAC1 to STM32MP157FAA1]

## STM32MP157DAC1
designator U?
part A pins: A7 PD5, A8 PA9, A11 PB3, A13 PA8, A19 JTDO-TRACESWO, A20 JTDI, AA4 PA1, AA6 PC1, AA7 PB1, AA10 PB13, AA18 PA11, AA19 PD13, AB1 PB11, AB3 PA0, AB5 PC0, AB6 PB0, AB7 PC5, AB8 PA7, AB10 PB8, AB16 USB_DM2, AB17 USB_DM1, AB18 USB_RREF, AB19 PA12, AC3 PA2, AC5 PB12, AC7 PC4, AC8 PA6, AC10 PD11, AC16 USB_DP2, AC17 USB_DP1, AC19 OTG_VBUS, B5 PD10, B6 PD4, B8 PD0, B9 PD1, B10 PB9, B11 PC7, B12 PB15, B13 PB4, B14 PC6, B19 NJTRST, B20 JTCK-SWCLK, C13 PB14, C19 PA15, C20 JTMS-SWDIO, D2 PD6, D10 PD7, D11 PB7, D12 PD2, D13 PC12, D14 PD3, D15 PC10, D16 PC11, D17 PC9, D18 PC8, J2 PD15, K1 PD9, K2 PC13, K3 PD8, L1 PC15-OSC32_OUT, L2 PC14-OSC32_IN, L3 PD14, N2 PA13, T2 PA14, U2 PA3, V3 PA5, V4 PA4, W2 PC3, Y2 PC2, Y3 PB10, Y8 PB5, Y14 PB6, Y16 PB2, Y17 PA10, Y18 PD12
part B pins: A2 PH5, A3 PE13, A4 PE11, A5 PF1, A10 PG6, A14 PF2, AA1 PG14, AA2 PG13, AA3 PH3, AA9 PE9, AA11 PE7, AA13 PF6, AA14 PF9, AB2 PG4, AB4 PH2, AB9 PG8, AB11 PG10, AB12 PF7, AC2 PG0, AC4 PF14, AC11 PF8, AC13 PE8, AC14 PG7, B1 PH15, B2 PH12, B3 PH4, B4 PE12, B7 PG15, C2 PH10, C3 PH14, C4 PH11, C5 PH9, C6 PE14, C8 PE1, C9 PE3, C10 PE6, C11 PE5, D1 PH13, D3 PE15, D5 PH8, D6 PE0, D7 PF5, D8 PF0, D9 PF4, D19 PE4, K4 PG12, P1 PH0-OSC_IN, P2 PH1-OSC_OUT, T4 PG3, U1 PF3, V2 PG2, W1 PG1, W4 PH7, Y1 PE2, Y4 PF15, Y5 PF13, Y6 PG5, Y7 PG11, Y9 PF12, Y10 PF11, Y11 PH6, Y12 PF10, Y13 PG9, Y15 PE10
part C pins: A16 DSI_CKN, A17 DSI_D1N, AB13 BYPASS_REG1V8, B15 DSI_D0N, B16 DSI_CKP, B17 DSI_D1P, C1 PI0, C15 DSI_D0P, E1 PI3, E2 PI2, E3 PI1, E4 PI4, F2 PI7, F3 PI5, F4 PI6, G1 PZ1, G2 PZ4, G3 PZ0, G4 PZ3, H1 PZ6, H2 PZ5, H4 PI9, J3 PZ7, J4 PZ2, L4 PI8, M2 BOOT2, M3 NRST, M4 NRST_CORE, N1 BOOT0, N3 PWR_LP, N4 BOOT1, P4 PI11, R2 PWR_ON, R3 PDR_ON, T1 PI10, T3 PDR_ON_CORE, U3 ANA0, U4 ANA1
part D pins: 1A2 VDDCORE, 1A3 VSS, 1A4 VDDCORE, 1A5 VSS, 1A6 VDDCORE, 1A7 VSS, 1A8 VDDQ_DDR, 1B1 VDDCORE, 1B2 VSS, 1B3 VDDCORE, 1B4 VSS, 1B5 VDDCORE, 1B6 VSS, 1B7 VDDQ_DDR, 1B8 VSS, 1B9 VDDQ_DDR, 1C1 VSS, 1C2 VDDCORE, 1C3 VSS, 1C4 VDDCORE, 1C5 VSS, 1C6 VDDCORE, 1C7 VSS, 1C8 VDDQ_DDR, 1C9 VSS, 1D1 VDDCORE, 1D2 VSS, 1D3 VDDCORE, 1D4 VSS, 1D5 VDDCORE, 1D6 VSS, 1D7 VDDCORE, 1D8 VSS, 1D9 VDDQ_DDR, 1E1 VSS, 1E2 VDDCORE, 1E3 VSS, 1E4 VDDCORE, 1E5 VSS, 1E6 VDDCORE, 1E7 VSS, 1E8 VDDQ_DDR, 1E9 VSS, 1F1 VBAT, 1F2 VSS, 1F3 VDD, 1F4 VSS, 1F5 VDDCORE, 1F6 VSS, 1F7 VDDCORE, 1F8 VSS, 1F9 VDDQ_DDR, 1G1 VSS_ANA, 1G2 VDD_ANA, 1G3 VSS, 1G4 VDD, 1G5 VSS, 1G6 VDDCORE, 1G7 VSS, 1G8 VDDQ_DDR, 1G9 VSS, 1H1 VDDA, 1H2 VSSA, 1H3 VDD, 1H4 VSS, 1H5 VDD, 1H6 VSS, 1H7 VDDCORE, 1H8 VSS, 1H9 VDDQ_DDR, 1J2 VDD_OTP, 1J3 VSS, 1J4 VDD, 1J5 VSS, 1J6 VDD, 1J7 VSS, 1J8 VDDQ_DDR, A1 VSS, A23 VSS, AA5 VSS, AA8 VSS, AA12 VSS, AA15 VDD3V3_USBHS, AA16 VSS_USBHS, AA17 VDD3V3_USBFS, AA21 VSS, AB14 VDDA1V8_REG, AB15 VDDA1V1_REG, AC1 VSS, AC23 VSS, B18 VDD_DSI, C7 VSS, C12 VSS, C14 VDDA1V8_DSI, C16 VSS_DSI, C17 VDD1V2_DSI_PHY, C18 VDD1V2_DSI_REG, C21 VSS, D4 VSS, F21 VSS, H3 VSS, K21 VSS, P3 VSS, P21 VSS, R4 VREF+, V21 VSS, W3 VSS
part E pins: A21 DDR_DQ20, A22 DDR_DQ23, AA20 DDR_DQM3, AA22 DDR_DQ31, AA23 DDR_DQ30, AB20 DDR_DQ27, AB21 DDR_DQ26, AB22 DDR_DQS3P, AB23 DDR_DQS3N, AC20 DDR_VREF, AC21 DDR_DQ29, AC22 DDR_DQ28, B21 DDR_DQ19, B22 DDR_DQ16, B23 DDR_DQS2N, C22 DDR_DQS2P, C23 DDR_DQM2, D20 DDR_RESETN, D21 DDR_DQ22, D22 DDR_DQ17, D23 DDR_DQ18, E20 DDR_A7, E21 DDR_DQ3, E22 DDR_DQ0, E23 DDR_DQ21, F20 DDR_A13, F22 DDR_DQ1, G20 DDR_A9, G21 DDR_DQ7, G22 DDR_DQS0P, G23 DDR_DQS0N, H20 DDR_A5, H21 DDR_DQ2, H22 DDR_DQ6, H23 DDR_DQM0, J20 DDR_A2, J21 DDR_DQ4, J22 DDR_DQ5, K20 DDR_DTO0, K22 DDR_A3, K23 DDR_ZQ, L20 DDR_A0, L21 DDR_DTO1, L22 DDR_ODT, L23 DDR_BA0, M20 DDR_WEN, M21 DDR_BA2, M22 DDR_CSN, N20 DDR_CASN, N21 DDR_RASN, N22 DDR_CLKP, N23 DDR_CLKN, P20 DDR_A15, P22 DDR_A1, P23 DDR_A12, R20 DDR_A11, R21 DDR_A14, R22 DDR_A10, T20 DDR_CKE, T21 DDR_DQ8, T22 DDR_DQ10, T23 DDR_DQ13, U20 DDR_BA1, U21 DDR_DQ9, U22 DDR_DQS1P, U23 DDR_DQS1N, V20 DDR_A4, V22 DDR_DQM1, W20 DDR_A6, W21 DDR_DQ11, W22 DDR_DQ14, W23 DDR_DQ12, Y19 DDR_ATO, Y20 DDR_A8, Y21 DDR_DQ15, Y22 DDR_DQ25, Y23 DDR_DQ24

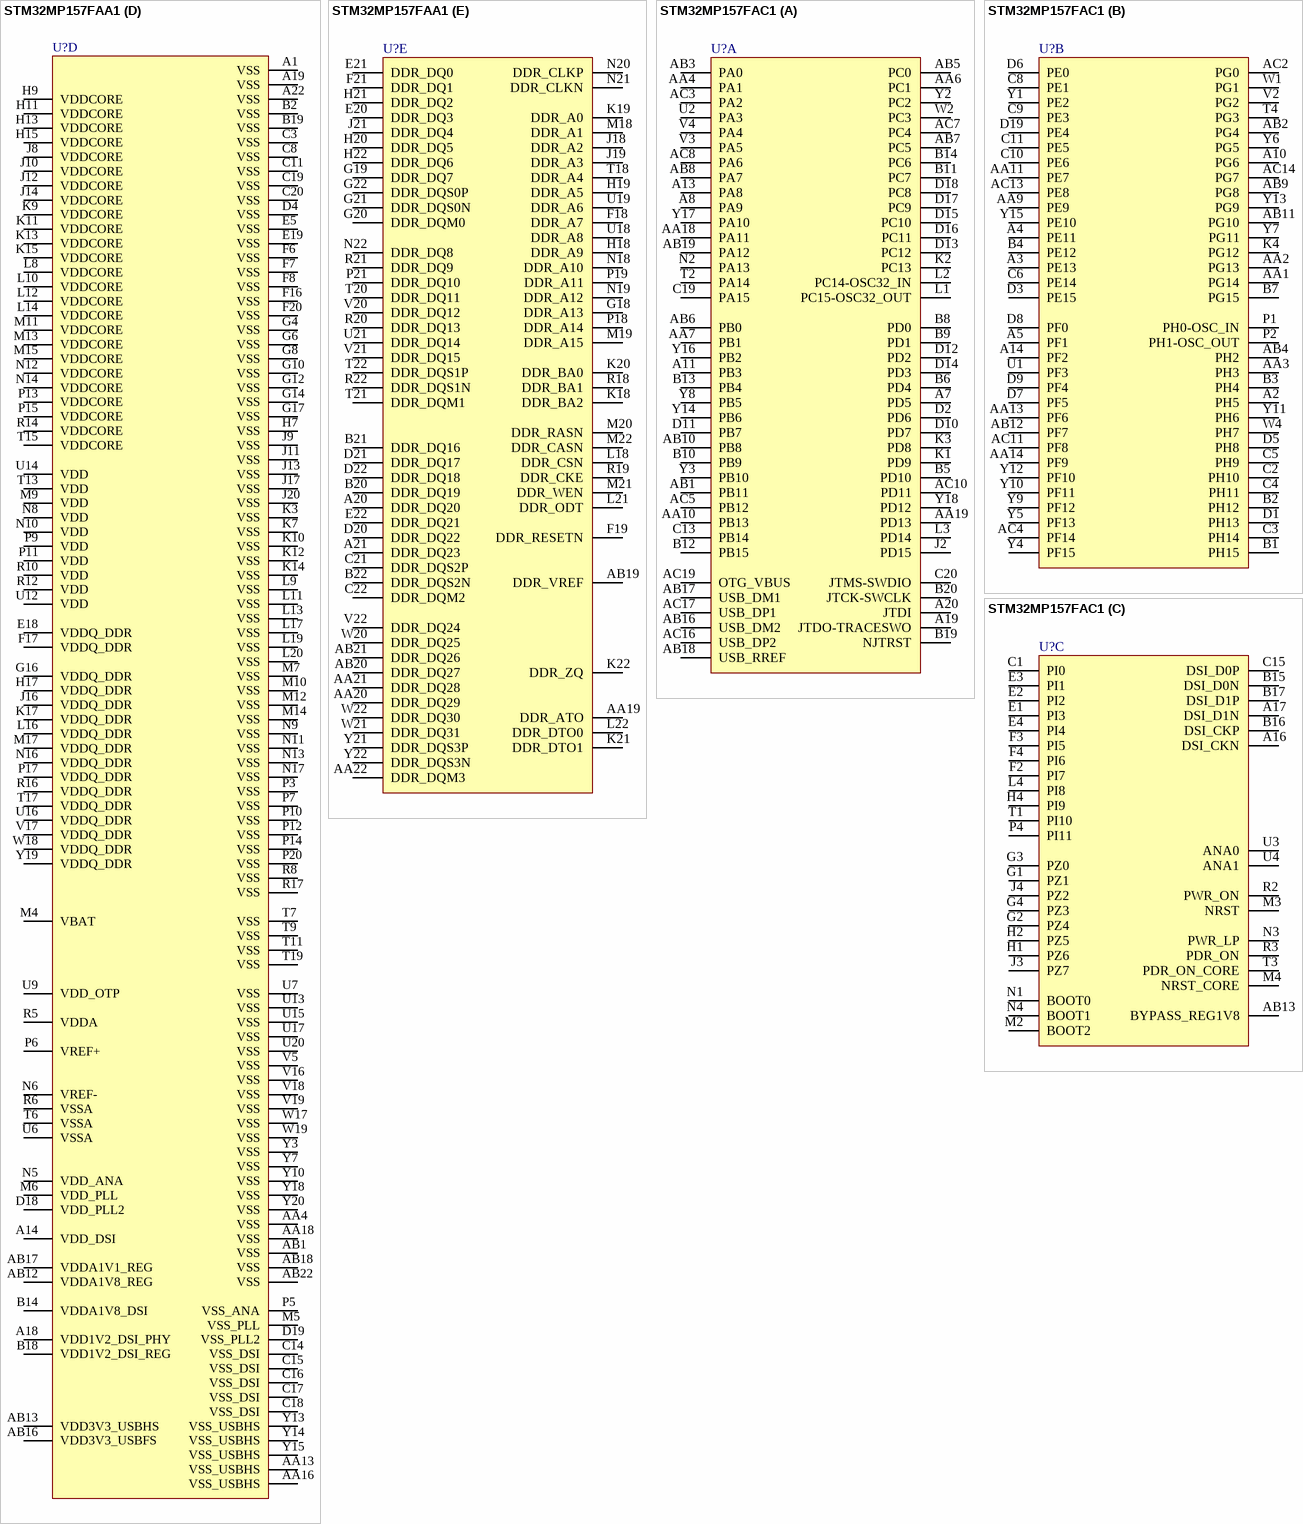
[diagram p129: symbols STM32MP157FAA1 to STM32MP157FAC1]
